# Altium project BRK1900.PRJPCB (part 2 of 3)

## Sheet Expansion-MC2.SchDoc: BRK1900 - Expansion MC2
size C; Organization: Opal Kelly; Address1: 13500 SW 72nd Ave STE 100; Address3: Portland, OR  97223; Address4: http://www.opalkelly.com; DocumentNumber: xxx; Revision: 1; SheetNumber: 3; SheetTotal: 9; PageSetup: Record=PageOptions¦CenterHorizontal=True¦CenterVertical=True¦PrintScale=0.52¦XCorrection=1.00¦YCorrection=1.00¦PrintKind=0¦BorderSize=5000000¦LeftOffset=0¦BottomOffset=0¦Orientation=2¦PaperLength=1000¦PaperWidth=1000¦Scale=100¦PaperSource=7¦PrintQuality=-4¦MediaType=1¦DitherType=10¦PaperKind=Letter¦PrintScaleMode=1
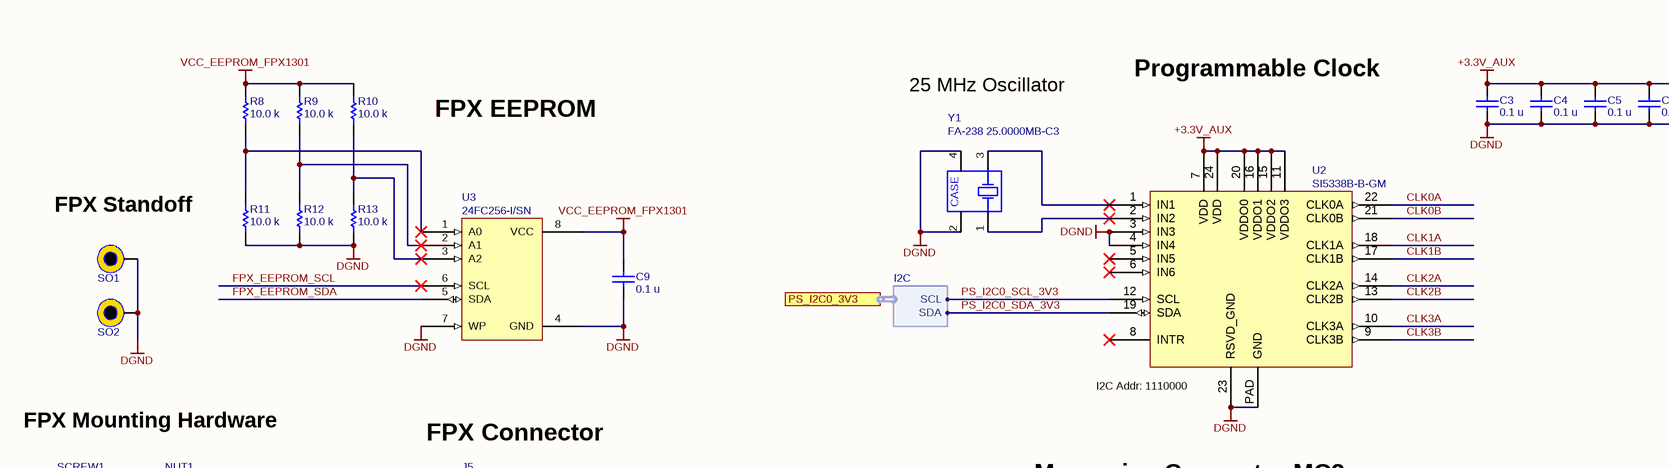
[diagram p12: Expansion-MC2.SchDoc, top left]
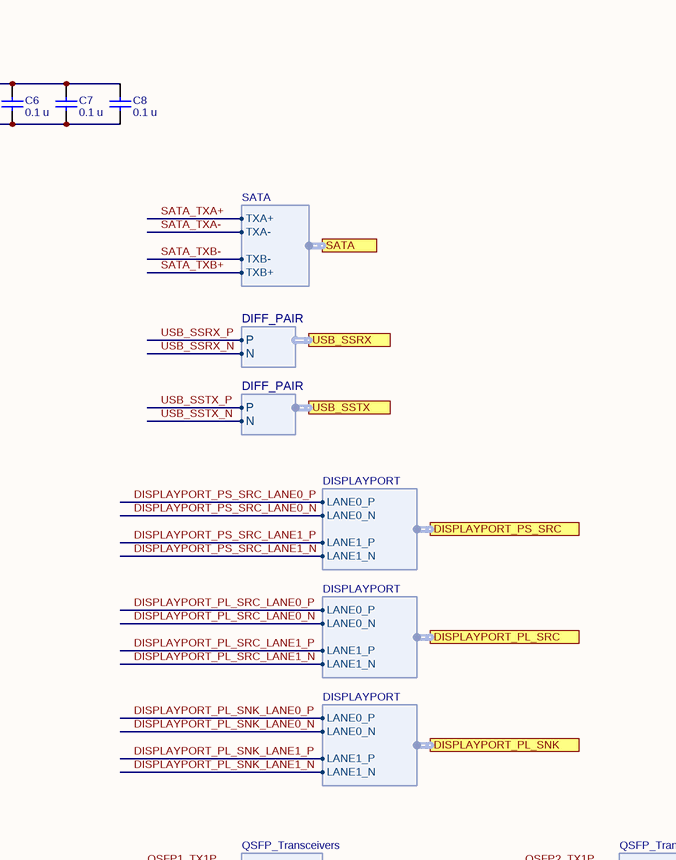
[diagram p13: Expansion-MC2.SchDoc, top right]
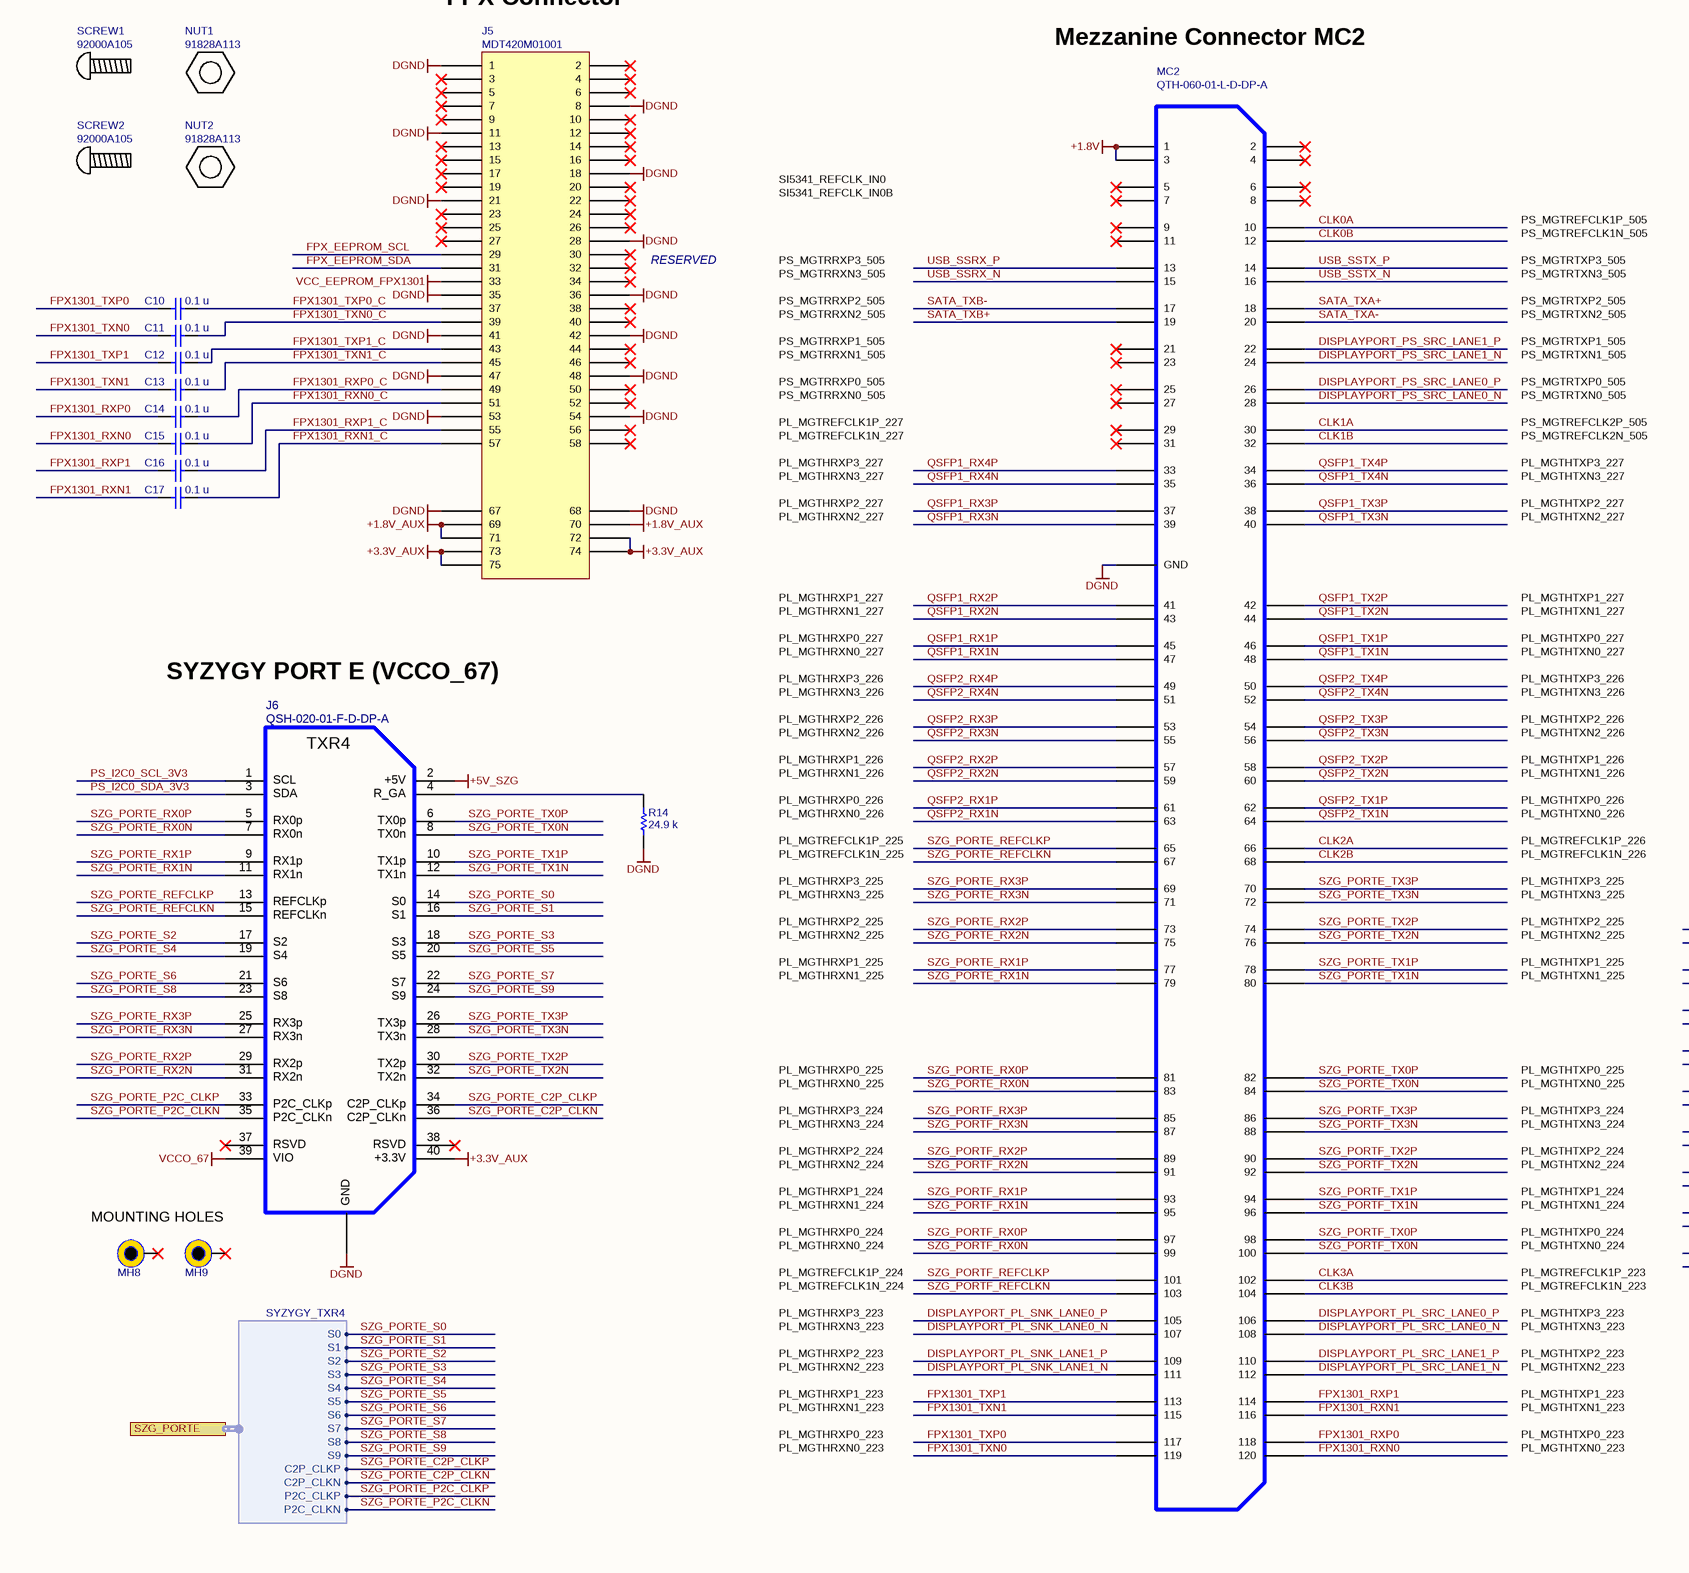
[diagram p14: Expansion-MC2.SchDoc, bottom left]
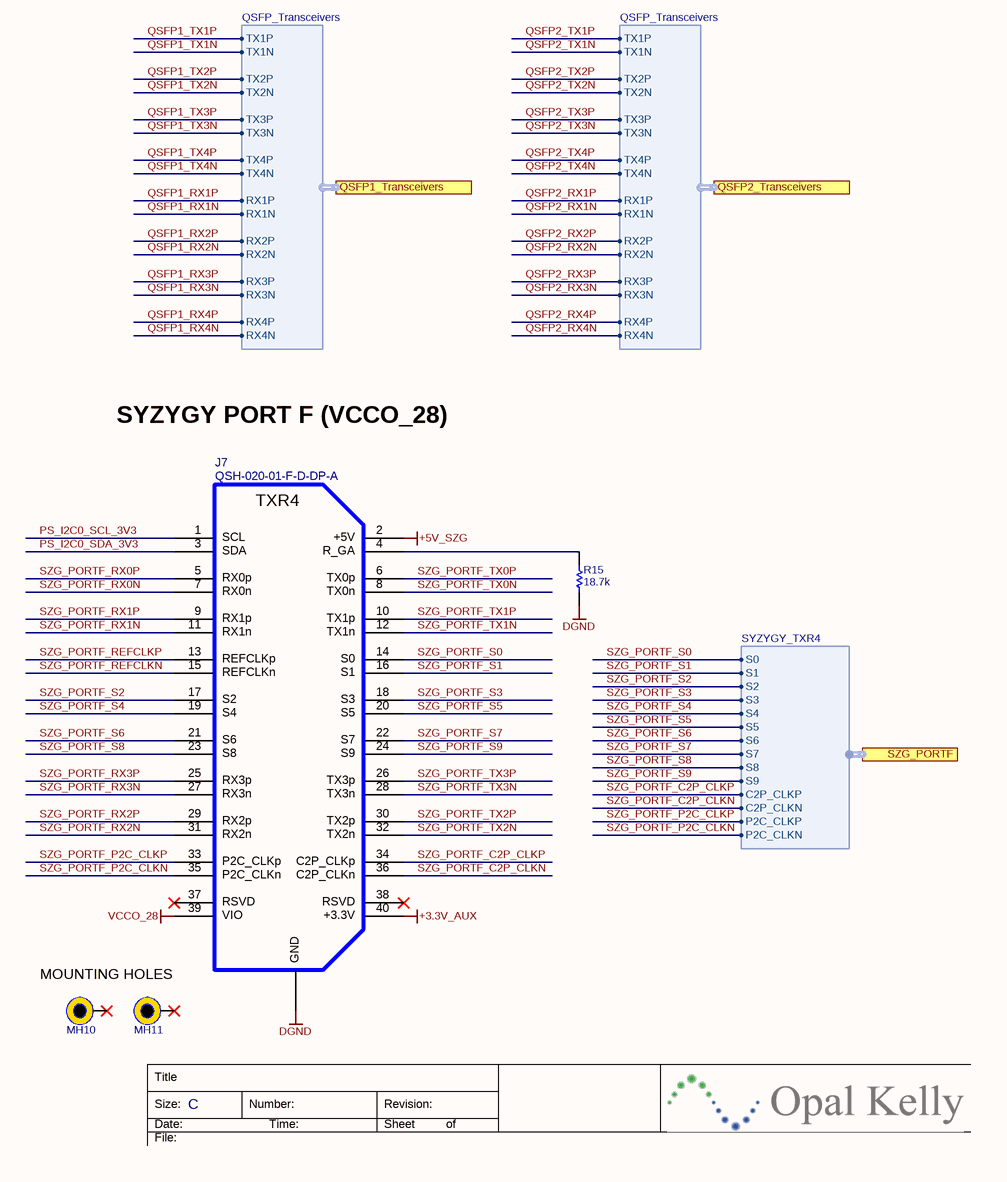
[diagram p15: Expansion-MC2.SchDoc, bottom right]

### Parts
C3  value 0.1 u  [CAPC1005X06A]  (hidden comment: C0402C104K8PACTU)
C4  value 0.1 u  [CAPC1005X06A]  (hidden comment: C0402C104K8PACTU)
C5  value 0.1 u  [CAPC1005X06A]  (hidden comment: C0402C104K8PACTU)
C6  value 0.1 u  [CAPC1005X06A]  (hidden comment: C0402C104K8PACTU)
C7  value 0.1 u  [CAPC1005X06A]  (hidden comment: C0402C104K8PACTU)
C8  value 0.1 u  [CAPC1005X06A]  (hidden comment: C0402C104K8PACTU)
C9  value 0.1 u  [CAPC1005X06A]  (hidden comment: C0402C104K8PACTU)
C10  value 0.1 u  [CAPC1005X06A]  (hidden comment: C0402C104K8PACTU)
C11  value 0.1 u  [CAPC1005X06A]  (hidden comment: C0402C104K8PACTU)
C12  value 0.1 u  [CAPC1005X06A]  (hidden comment: C0402C104K8PACTU)
C13  value 0.1 u  [CAPC1005X06A]  (hidden comment: C0402C104K8PACTU)
C14  value 0.1 u  [CAPC1005X06A]  (hidden comment: C0402C104K8PACTU)
C15  value 0.1 u  [CAPC1005X06A]  (hidden comment: C0402C104K8PACTU)
C16  value 0.1 u  [CAPC1005X06A]  (hidden comment: C0402C104K8PACTU)
C17  value 0.1 u  [CAPC1005X06A]  (hidden comment: C0402C104K8PACTU)
J5  MDT420M01001  [M2-Connector_M-Keying]
J6  QSH-020-01-F-D-DP-A  [QSH-020-01-X-D-DP-A-L]
J7  QSH-020-01-F-D-DP-A  [QSH-020-01-X-D-DP-A-L]
MC2  QTH-060-01-L-D-DP-A  [QTH-060-01-X-D-DP-A]
MH8  MTG  [MTG-2.7/5.0-PTH]  (value not drawn)
MH9  MTG  [MTG-2.7/5.0-PTH]  (value not drawn)
MH10  MTG  [MTG-2.7/5.0-PTH]  (value not drawn)
MH11  MTG  [MTG-2.7/5.0-PTH]  (value not drawn)
NUT1  91828A113  (mechanical)
NUT2  91828A113  (mechanical)
R8  value 10.0 k  [RESC1005X06A]  (hidden comment: CRCW040210K0FKED)
R9  value 10.0 k  [RESC1005X06A]  (hidden comment: CRCW040210K0FKED)
R10  value 10.0 k  [RESC1005X06A]  (hidden comment: CRCW040210K0FKED)
R11  value 10.0 k  [RESC1005X06A]  (hidden comment: CRCW040210K0FKED)
R12  value 10.0 k  [RESC1005X06A]  (hidden comment: CRCW040210K0FKED)
R13  value 10.0 k  [RESC1005X06A]  (hidden comment: CRCW040210K0FKED)
R14  value 24.9 k  [RESC1005X06A]  (hidden comment: CRCW040224K9FKED)
R15  value 18.7k  [RESC1005X06A]  (hidden comment: CRCW040218K7FKED)
SCREW1  92000A105  (mechanical)
SCREW2  92000A105  (mechanical)
SO1  Standoff  [9774025151R]  (value not drawn)
SO2  Standoff  [9774025151R]  (value not drawn)
U2  SI5338B-B-GM  [Si5338]
U3  24FC256-I/SN  [SO-G8]
Y1  FA-238 25.0000MB-C3  [OSC_SMD_32x25]

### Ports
DISPLAYPORT_PL_SNK (harness DISPLAYPORT), DISPLAYPORT_PL_SRC (harness DISPLAYPORT), DISPLAYPORT_PS_SRC (harness DISPLAYPORT), PS_I2C0_3V3 (harness I2C), QSFP1_Transceivers (harness QSFP_Transceivers), QSFP2_Transceivers (harness QSFP_Transceivers), SATA (harness SATA), SZG_PORTE (harness SYZYGY_TXR4), SZG_PORTF (harness SYZYGY_TXR4), USB_SSRX (harness DIFF_PAIR), USB_SSTX (harness DIFF_PAIR)

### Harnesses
QSFP_Transceivers: TX1P, TX1N, TX2P, TX2N, TX3P, TX3N, TX4P, TX4N, RX1P, RX1N, RX2P, RX2N, RX3P, RX3N, RX4P, RX4N
SATA: TXA+, TXA-, TXB-, TXB+
DIFF_PAIR: P, N
DISPLAYPORT: LANE0_P, LANE0_N, LANE1_P, LANE1_N
SYZYGY_TXR4: S0, S1, S2, S3, S4, S5, S6, S7, S8, S9, C2P_CLKP, C2P_CLKN, P2C_CLKP, P2C_CLKN
I2C: SCL, SDA

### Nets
+1.8V: MC2.1 MC2.3
+1.8V_AUX: J5.69 J5.70 J5.71
+3.3V_AUX: C3.2 C4.2 C5.2 C6.2 C7.2 C8.2 J5.72 J5.73 J5.74 J5.75 J6.40 J7.40 U2.7(VDD) U2.11(VDDO3) U2.15(VDDO2) U2.16(VDDO1) U2.20(VDDO0) U2.24(VDD)
+5V_SZG: J6.2 J7.2
DGND: C3.1 C4.1 C5.1 C6.1 C7.1 C8.1 C9.1 J5.1 J5.8 J5.11 J5.18 J5.21 J5.28 J5.35 J5.36 J5.41 J5.42 J5.47 J5.48 J5.53 J5.54 J5.67 J5.68 J6.0(GND) J7.0(GND) MC2.0(GND) R11.1 R12.1 R13.1 R14.1 R15.1 SO1.1 SO2.1 U2.3(IN3) U2.4(IN4) U2.23(RSVD_GND) U2.PAD(GND) U3.4(GND) U3.7(WP) Y1.2(CASE) Y1.4(CASE)
VCC_EEPROM_FPX1301: C9.2 J5.33 R8.2 R9.2 R10.2 U3.8(VCC)
VCCO_28: J7.39
VCCO_67: J6.39
CLK0A: MC2.10 U2.22(CLK0A)
CLK0B: MC2.12 U2.21(CLK0B)
CLK1A: MC2.30 U2.18(CLK1A)
CLK1B: MC2.32 U2.17(CLK1B)
CLK2A: MC2.66 U2.14(CLK2A)
CLK2B: MC2.68 U2.13(CLK2B)
CLK3A: MC2.102 U2.10(CLK3A)
CLK3B: MC2.104 U2.9(CLK3B)
DISPLAYPORT_PL_SNK_LANE0_N: MC2.107 ; port DISPLAYPORT_PL_SNK.LANE0_N
DISPLAYPORT_PL_SNK_LANE0_P: MC2.105 ; port DISPLAYPORT_PL_SNK.LANE0_P
DISPLAYPORT_PL_SNK_LANE1_N: MC2.111 ; port DISPLAYPORT_PL_SNK.LANE1_N
DISPLAYPORT_PL_SNK_LANE1_P: MC2.109 ; port DISPLAYPORT_PL_SNK.LANE1_P
DISPLAYPORT_PL_SRC_LANE0_N: MC2.108 ; port DISPLAYPORT_PL_SRC.LANE0_N
DISPLAYPORT_PL_SRC_LANE0_P: MC2.106 ; port DISPLAYPORT_PL_SRC.LANE0_P
DISPLAYPORT_PL_SRC_LANE1_N: MC2.112 ; port DISPLAYPORT_PL_SRC.LANE1_N
DISPLAYPORT_PL_SRC_LANE1_P: MC2.110 ; port DISPLAYPORT_PL_SRC.LANE1_P
DISPLAYPORT_PS_SRC_LANE0_N: MC2.28 ; port DISPLAYPORT_PS_SRC.LANE0_N
DISPLAYPORT_PS_SRC_LANE0_P: MC2.26 ; port DISPLAYPORT_PS_SRC.LANE0_P
DISPLAYPORT_PS_SRC_LANE1_N: MC2.24 ; port DISPLAYPORT_PS_SRC.LANE1_N
DISPLAYPORT_PS_SRC_LANE1_P: MC2.22 ; port DISPLAYPORT_PS_SRC.LANE1_P
FPX1301_RXN0: C15.1 MC2.120
FPX1301_RXN0_C: C15.2 J5.51
FPX1301_RXN1: C17.1 MC2.116
FPX1301_RXN1_C: C17.2 J5.57
FPX1301_RXP0: C14.1 MC2.118
FPX1301_RXP0_C: C14.2 J5.49
FPX1301_RXP1: C16.1 MC2.114
FPX1301_RXP1_C: C16.2 J5.55
FPX1301_TXN0: C11.1 MC2.119
FPX1301_TXN0_C: C11.2 J5.39
FPX1301_TXN1: C13.1 MC2.115
FPX1301_TXN1_C: C13.2 J5.45
FPX1301_TXP0: C10.1 MC2.117
FPX1301_TXP0_C: C10.2 J5.37
FPX1301_TXP1: C12.1 MC2.113
FPX1301_TXP1_C: C12.2 J5.43
FPX_EEPROM_SCL: J5.29 U3.6(SCL)
FPX_EEPROM_SDA: J5.31 U3.5(SDA)
PS_I2C0_SCL_3V3: J6.1 J7.1 U2.12(SCL) ; port PS_I2C0_3V3.SCL
PS_I2C0_SDA_3V3: J6.3 J7.3 U2.19(SDA) ; port PS_I2C0_3V3.SDA
QSFP1_RX1N: MC2.47 ; port QSFP1_Transceivers.RX1N
QSFP1_RX1P: MC2.45 ; port QSFP1_Transceivers.RX1P
QSFP1_RX2N: MC2.43 ; port QSFP1_Transceivers.RX2N
QSFP1_RX2P: MC2.41 ; port QSFP1_Transceivers.RX2P
QSFP1_RX3N: MC2.39 ; port QSFP1_Transceivers.RX3N
QSFP1_RX3P: MC2.37 ; port QSFP1_Transceivers.RX3P
QSFP1_RX4N: MC2.35 ; port QSFP1_Transceivers.RX4N
QSFP1_RX4P: MC2.33 ; port QSFP1_Transceivers.RX4P
QSFP1_TX1N: MC2.48 ; port QSFP1_Transceivers.TX1N
QSFP1_TX1P: MC2.46 ; port QSFP1_Transceivers.TX1P
QSFP1_TX2N: MC2.44 ; port QSFP1_Transceivers.TX2N
QSFP1_TX2P: MC2.42 ; port QSFP1_Transceivers.TX2P
QSFP1_TX3N: MC2.40 ; port QSFP1_Transceivers.TX3N
QSFP1_TX3P: MC2.38 ; port QSFP1_Transceivers.TX3P
QSFP1_TX4N: MC2.36 ; port QSFP1_Transceivers.TX4N
QSFP1_TX4P: MC2.34 ; port QSFP1_Transceivers.TX4P
QSFP2_RX1N: MC2.63 ; port QSFP2_Transceivers.RX1N
QSFP2_RX1P: MC2.61 ; port QSFP2_Transceivers.RX1P
QSFP2_RX2N: MC2.59 ; port QSFP2_Transceivers.RX2N
QSFP2_RX2P: MC2.57 ; port QSFP2_Transceivers.RX2P
QSFP2_RX3N: MC2.55 ; port QSFP2_Transceivers.RX3N
QSFP2_RX3P: MC2.53 ; port QSFP2_Transceivers.RX3P
QSFP2_RX4N: MC2.51 ; port QSFP2_Transceivers.RX4N
QSFP2_RX4P: MC2.49 ; port QSFP2_Transceivers.RX4P
QSFP2_TX1N: MC2.64 ; port QSFP2_Transceivers.TX1N
QSFP2_TX1P: MC2.62 ; port QSFP2_Transceivers.TX1P
QSFP2_TX2N: MC2.60 ; port QSFP2_Transceivers.TX2N
QSFP2_TX2P: MC2.58 ; port QSFP2_Transceivers.TX2P
QSFP2_TX3N: MC2.56 ; port QSFP2_Transceivers.TX3N
QSFP2_TX3P: MC2.54 ; port QSFP2_Transceivers.TX3P
QSFP2_TX4N: MC2.52 ; port QSFP2_Transceivers.TX4N
QSFP2_TX4P: MC2.50 ; port QSFP2_Transceivers.TX4P
SATA_TXA+: MC2.18 ; port SATA.TXA+
SATA_TXA-: MC2.20 ; port SATA.TXA-
SATA_TXB+: MC2.19 ; port SATA.TXB+
SATA_TXB-: MC2.17 ; port SATA.TXB-
SZG_PORTE_C2P_CLKN: J6.36 ; port SZG_PORTE.C2P_CLKN
SZG_PORTE_C2P_CLKP: J6.34 ; port SZG_PORTE.C2P_CLKP
SZG_PORTE_P2C_CLKN: J6.35 ; port SZG_PORTE.P2C_CLKN
SZG_PORTE_P2C_CLKP: J6.33 ; port SZG_PORTE.P2C_CLKP
SZG_PORTE_REFCLKN: J6.15 MC2.67
SZG_PORTE_REFCLKP: J6.13 MC2.65
SZG_PORTE_RX0N: J6.7 MC2.83
SZG_PORTE_RX0P: J6.5 MC2.81
SZG_PORTE_RX1N: J6.11 MC2.79
SZG_PORTE_RX1P: J6.9 MC2.77
SZG_PORTE_RX2N: J6.31 MC2.75
SZG_PORTE_RX2P: J6.29 MC2.73
SZG_PORTE_RX3N: J6.27 MC2.71
SZG_PORTE_RX3P: J6.25 MC2.69
SZG_PORTE_S0: J6.14 ; port SZG_PORTE.S0
SZG_PORTE_S1: J6.16 ; port SZG_PORTE.S1
SZG_PORTE_S2: J6.17 ; port SZG_PORTE.S2
SZG_PORTE_S3: J6.18 ; port SZG_PORTE.S3
SZG_PORTE_S4: J6.19 ; port SZG_PORTE.S4
SZG_PORTE_S5: J6.20 ; port SZG_PORTE.S5
SZG_PORTE_S6: J6.21 ; port SZG_PORTE.S6
SZG_PORTE_S7: J6.22 ; port SZG_PORTE.S7
SZG_PORTE_S8: J6.23 ; port SZG_PORTE.S8
SZG_PORTE_S9: J6.24 ; port SZG_PORTE.S9
SZG_PORTE_TX0N: J6.8 MC2.84
SZG_PORTE_TX0P: J6.6 MC2.82
SZG_PORTE_TX1N: J6.12 MC2.80
SZG_PORTE_TX1P: J6.10 MC2.78
SZG_PORTE_TX2N: J6.32 MC2.76
SZG_PORTE_TX2P: J6.30 MC2.74
SZG_PORTE_TX3N: J6.28 MC2.72
SZG_PORTE_TX3P: J6.26 MC2.70
SZG_PORTF_C2P_CLKN: J7.36 ; port SZG_PORTF.C2P_CLKN
SZG_PORTF_C2P_CLKP: J7.34 ; port SZG_PORTF.C2P_CLKP
SZG_PORTF_P2C_CLKN: J7.35 ; port SZG_PORTF.P2C_CLKN
SZG_PORTF_P2C_CLKP: J7.33 ; port SZG_PORTF.P2C_CLKP
SZG_PORTF_REFCLKN: J7.15 MC2.103
SZG_PORTF_REFCLKP: J7.13 MC2.101
SZG_PORTF_RX0N: J7.7 MC2.99
SZG_PORTF_RX0P: J7.5 MC2.97
SZG_PORTF_RX1N: J7.11 MC2.95
SZG_PORTF_RX1P: J7.9 MC2.93
SZG_PORTF_RX2N: J7.31 MC2.91
SZG_PORTF_RX2P: J7.29 MC2.89
SZG_PORTF_RX3N: J7.27 MC2.87
SZG_PORTF_RX3P: J7.25 MC2.85
SZG_PORTF_S0: J7.14 ; port SZG_PORTF.S0
SZG_PORTF_S1: J7.16 ; port SZG_PORTF.S1
SZG_PORTF_S2: J7.17 ; port SZG_PORTF.S2
SZG_PORTF_S3: J7.18 ; port SZG_PORTF.S3
SZG_PORTF_S4: J7.19 ; port SZG_PORTF.S4
SZG_PORTF_S5: J7.20 ; port SZG_PORTF.S5
SZG_PORTF_S6: J7.21 ; port SZG_PORTF.S6
SZG_PORTF_S7: J7.22 ; port SZG_PORTF.S7
SZG_PORTF_S8: J7.23 ; port SZG_PORTF.S8
SZG_PORTF_S9: J7.24 ; port SZG_PORTF.S9
SZG_PORTF_TX0N: J7.8 MC2.100
SZG_PORTF_TX0P: J7.6 MC2.98
SZG_PORTF_TX1N: J7.12 MC2.96
SZG_PORTF_TX1P: J7.10 MC2.94
SZG_PORTF_TX2N: J7.32 MC2.92
SZG_PORTF_TX2P: J7.30 MC2.90
SZG_PORTF_TX3N: J7.28 MC2.88
SZG_PORTF_TX3P: J7.26 MC2.86
USB_SSRX_N: MC2.15 ; port USB_SSRX.N
USB_SSRX_P: MC2.13 ; port USB_SSRX.P
USB_SSTX_N: MC2.16 ; port USB_SSTX.N
USB_SSTX_P: MC2.14 ; port USB_SSTX.P
NetJ6_4: J6.4 R14.2
NetJ7_4: J7.4 R15.2
NetR8_1: R8.1 R11.2 U3.1(A0)
NetR9_1: R9.1 R12.2 U3.2(A1)
NetR10_1: R10.1 R13.2 U3.3(A2)
NetU2_1: U2.1(IN1) Y1.3(OSC2)
NetU2_2: U2.2(IN2) Y1.1(OSC1)

Not connected (* = marked no-connect by the designer): J5 2* 3* 4* 5* 6* 7* 9* 10* 12* 13* 14* 15* 16* 17* 19* 20* 22* 23* 24* 25* 26* 27* 30* 32* 34* 38* 40* 44* 46* 50* 52* 56* 58*; J6 37* 38*; J7 37* 38*; MC2 2* 4* 5* 6* 7* 8* 9* 11* 21* 23* 25* 27* 29* 31*; MH8 1*; MH9 1*; MH10 1*; MH11 1*; U2 5(IN5)* 6(IN6)* 8(INTR)*

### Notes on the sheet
- Programmable Clock
- FPX EEPROM
- 25 MHz Oscillator
- FPX Standoff
- (near U2) I2C Addr: 1110000
- FPX Mounting Hardware
- FPX Connector
- Mezzanine Connector MC2
- SI5341_REFCLK_IN0
- SI5341_REFCLK_IN0B
- PS_MGTREFCLK1P_505
- PS_MGTREFCLK1N_505
- RESERVED
- PS_MGTRRXP3_505
- PS_MGTRRXN3_505
- PS_MGTRRXP2_505
- PS_MGTRRXN2_505
- PS_MGTRTXP3_505
- PS_MGTRTXN3_505
- PS_MGTRTXP2_505
- PS_MGTRTXN2_505
- PS_MGTRRXP1_505
- PS_MGTRRXN1_505
- PS_MGTRRXP0_505
- PS_MGTRTXP1_505
- PS_MGTRTXN1_505
- PS_MGTRTXP0_505
- PS_MGTRRXN0_505
- PL_MGTREFCLK1P_227
- PL_MGTREFCLK1N_227
- PS_MGTRTXN0_505
- PS_MGTREFCLK2P_505
- PS_MGTREFCLK2N_505
- PL_MGTHRXP3_227
- PL_MGTHRXN3_227
- PL_MGTHRXP2_227
- PL_MGTHRXN2_227
- PL_MGTHTXP3_227
- PL_MGTHTXN3_227
- PL_MGTHTXP2_227
- PL_MGTHTXN2_227
- PL_MGTHRXN1_227
- PL_MGTHRXP1_227
- PL_MGTHRXP0_227
- PL_MGTHRXN0_227
- PL_MGTHTXP1_227
- PL_MGTHTXN1_227
- PL_MGTHTXP0_227
- PL_MGTHTXN0_227
- SYZYGY PORT E (VCCO_67)
- PL_MGTHRXP3_226
- PL_MGTHRXN3_226
- PL_MGTHRXP2_226
- PL_MGTHTXP3_226
- PL_MGTHTXN3_226
- PL_MGTHTXP2_226
- PL_MGTHRXN2_226
- PL_MGTHRXP1_226
- PL_MGTHRXN1_226
- PL_MGTHTXN2_226
- PL_MGTHTXP1_226
- PL_MGTHTXN1_226
- PL_MGTHRXP0_226
- PL_MGTHRXN0_226
- PL_MGTREFCLK1P_225
- PL_MGTREFCLK1N_225
- PL_MGTHTXP0_226
- PL_MGTHTXN0_226
- PL_MGTREFCLK1P_226
- PL_MGTREFCLK1N_226
- SYZYGY PORT F (VCCO_28)
- PL_MGTHRXP3_225
- PL_MGTHRXN3_225
- PL_MGTHRXP2_225
- PL_MGTHTXP3_225
- PL_MGTHTXN3_225
- PL_MGTHTXP2_225
- PL_MGTHRXN2_225
- PL_MGTHRXP1_225
- PL_MGTHRXN1_225
- PL_MGTHTXN2_225
- PL_MGTHTXP1_225
- PL_MGTHTXN1_225
- PL_MGTHRXP0_225
- PL_MGTHRXN0_225
- PL_MGTHRXP3_224
- PL_MGTHRXN3_224
- PL_MGTHTXP0_225
- PL_MGTHTXN0_225
- PL_MGTHTXP3_224
- PL_MGTHTXN3_224
- PL_MGTHRXP2_224
- PL_MGTHRXN2_224
- PL_MGTHRXP1_224
- PL_MGTHTXP2_224
- PL_MGTHTXN2_224
- PL_MGTHTXP1_224
- MOUNTING HOLES
- PL_MGTHRXN1_224
- PL_MGTHRXP0_224
- PL_MGTHRXN0_224
- PL_MGTHTXN1_224
- PL_MGTHTXP0_224
- PL_MGTHTXN0_224
- PL_MGTREFCLK1P_224
- PL_MGTREFCLK1N_224
- PL_MGTHRXP3_223
- PL_MGTHRXN3_223
- PL_MGTREFCLK1P_223
- PL_MGTREFCLK1N_223
- PL_MGTHTXP3_223
- PL_MGTHTXN3_223
- PL_MGTHRXP2_223
- PL_MGTHRXN2_223
- PL_MGTHRXP1_223
- PL_MGTHTXP2_223
- PL_MGTHTXN2_223
- PL_MGTHTXP1_223
- PL_MGTHRXN1_223
- PL_MGTHRXP0_223
- PL_MGTHRXN0_223
- PL_MGTHTXN1_223
- PL_MGTHTXP0_223
- PL_MGTHTXN0_223
- Title
- Size:
- Date:
- File:
- C
- Number:
- Time:
- Revision:
- Sheet
- of

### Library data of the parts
C3-C8 C10-C17 = 000070: Partnumber: 000070; manufacturer: Kemet; ValueFloat: 1E-7; x_tolerance: 10
C9 = 000070: Ceramic capacitor; Partnumber: 000070; manufacturer: Kemet; ValueFloat: 1E-7; x_tolerance: 10
J5 = 001722: M.2 (NGFF) edge card connector, 4.2 mm height, M keying; Partnumber: 001722; manufacturer: Amphenol
J6 J7 = 000694: 0.5mm hi-speed, high-density socket (male); Partnumber: 000694; manufacturer: Samtec
MC2 = 001769: Partnumber: 001769; manufacturer: Samtec
MH8-MH11 = MTG: Mounting hole; partnumber: ALIGNI_IGNORE
NUT1 NUT2 = NUT: M2.5 hex nut; Manufacturer: McMaster-Carr; partnumber: 001810
R8-R13 = 001521: Thick-film resistor; Partnumber: 001521; manufacturer: Vishay; ValueFloat: 10000; x_tolerance: 1
R14 = 000934: Partnumber: 000934; manufacturer: Vishay; ValueFloat: 24900; x_tolerance: 1
R15 = 001783: Partnumber: 001783; manufacturer: Vishay; ValueFloat: 18700; x_tolerance: 1
SCREW1 SCREW2 = SCREW: Metric Pan Head Phil Machine Screw; Manufacturer: McMaster-Carr; partnumber: 001811
SO1 SO2 = 001726: Mounting hole; Partnumber: 001726; manufacturer: Wurth; id: 224568; inventory_price: 0.75
U2 = 001741: Partnumber: 001741; manufacturer: Silicon Labs
U3 = 000842: EEPROM; Partnumber: 000842; manufacturer: Microchip
Y1 = 001742: Partnumber: 001742; manufacturer: Epson

## Sheet Expansion-MC3.SchDoc: BRK1900 - Expansion MC3
size C; Organization: Opal Kelly; Address1: 13500 SW 72nd Ave STE 100; Address3: Portland, OR  97223; Address4: http://www.opalkelly.com; DocumentNumber: xxx; Revision: 1; SheetNumber: 4; SheetTotal: 9; PageSetup: Record=PageOptions¦CenterHorizontal=True¦CenterVertical=True¦PrintScale=0.52¦XCorrection=1.00¦YCorrection=1.00¦PrintKind=0¦BorderSize=5000000¦LeftOffset=0¦BottomOffset=0¦Orientation=2¦PaperLength=1000¦PaperWidth=1000¦Scale=100¦PaperSource=7¦PrintQuality=-4¦MediaType=1¦DitherType=10¦PaperKind=Letter¦PrintScaleMode=1
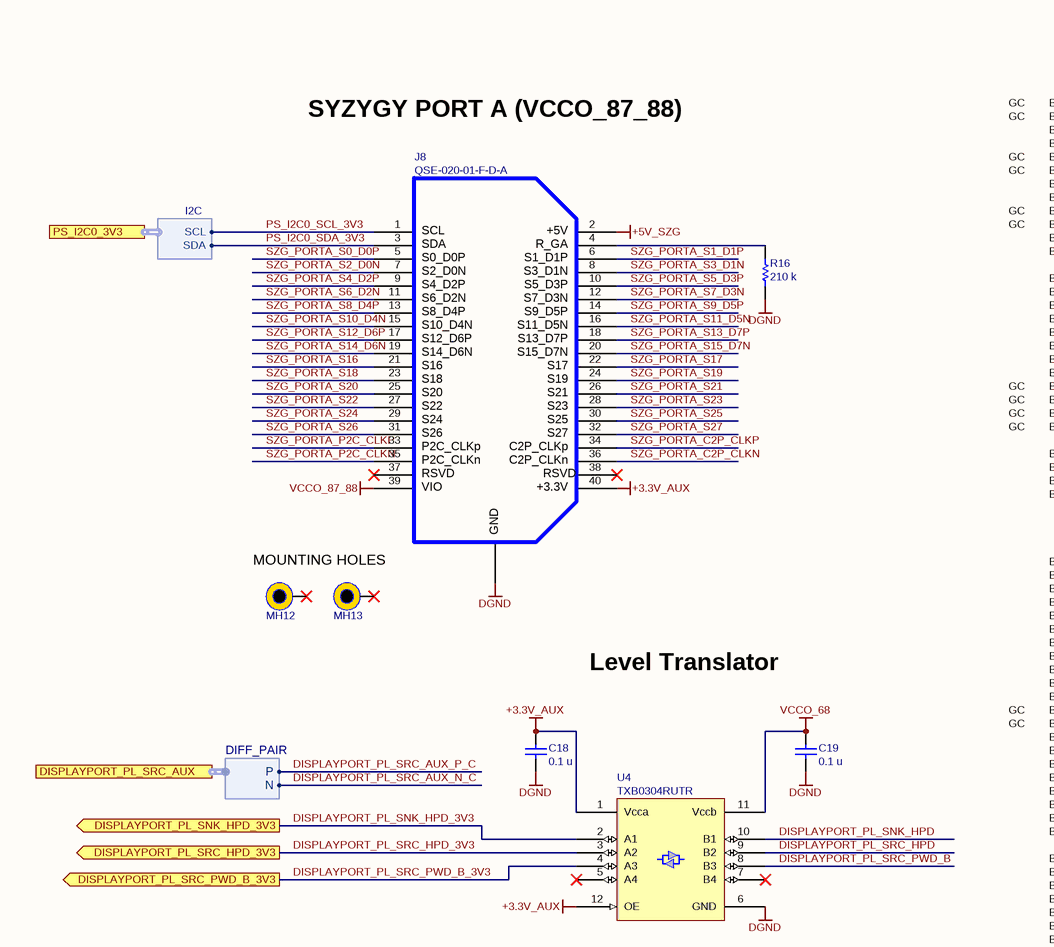
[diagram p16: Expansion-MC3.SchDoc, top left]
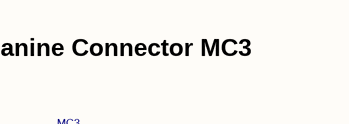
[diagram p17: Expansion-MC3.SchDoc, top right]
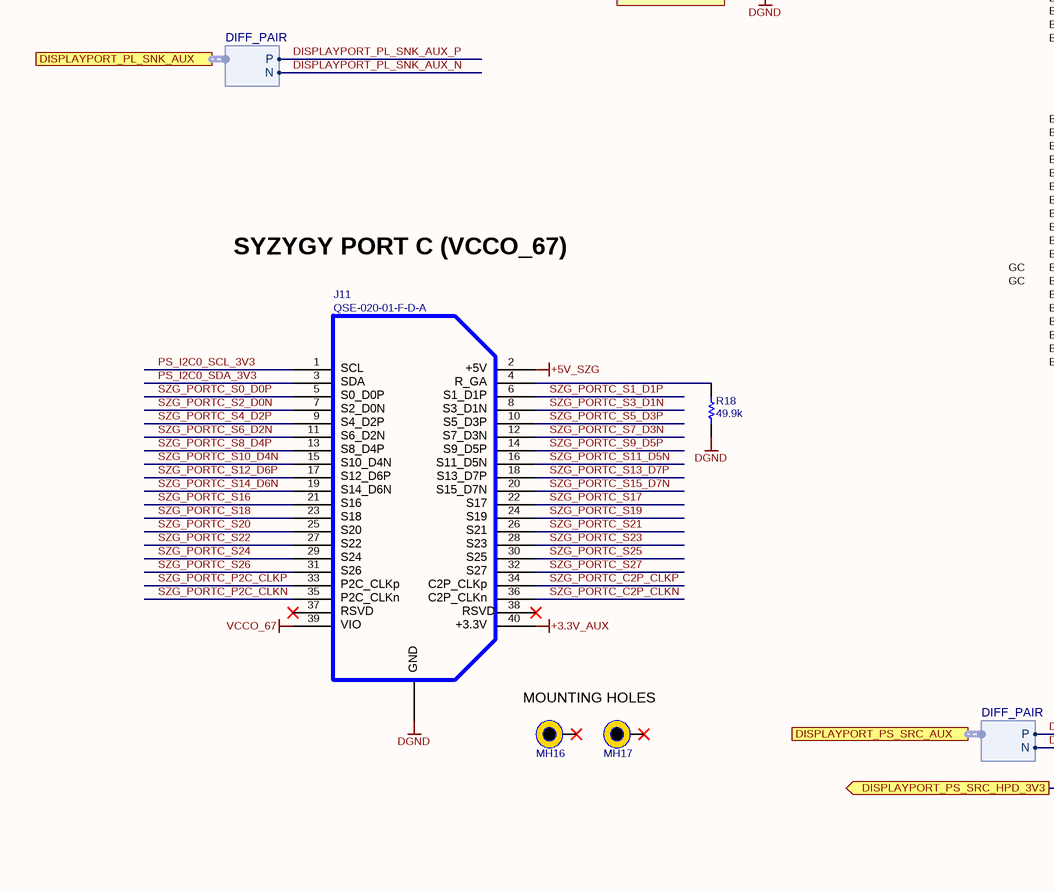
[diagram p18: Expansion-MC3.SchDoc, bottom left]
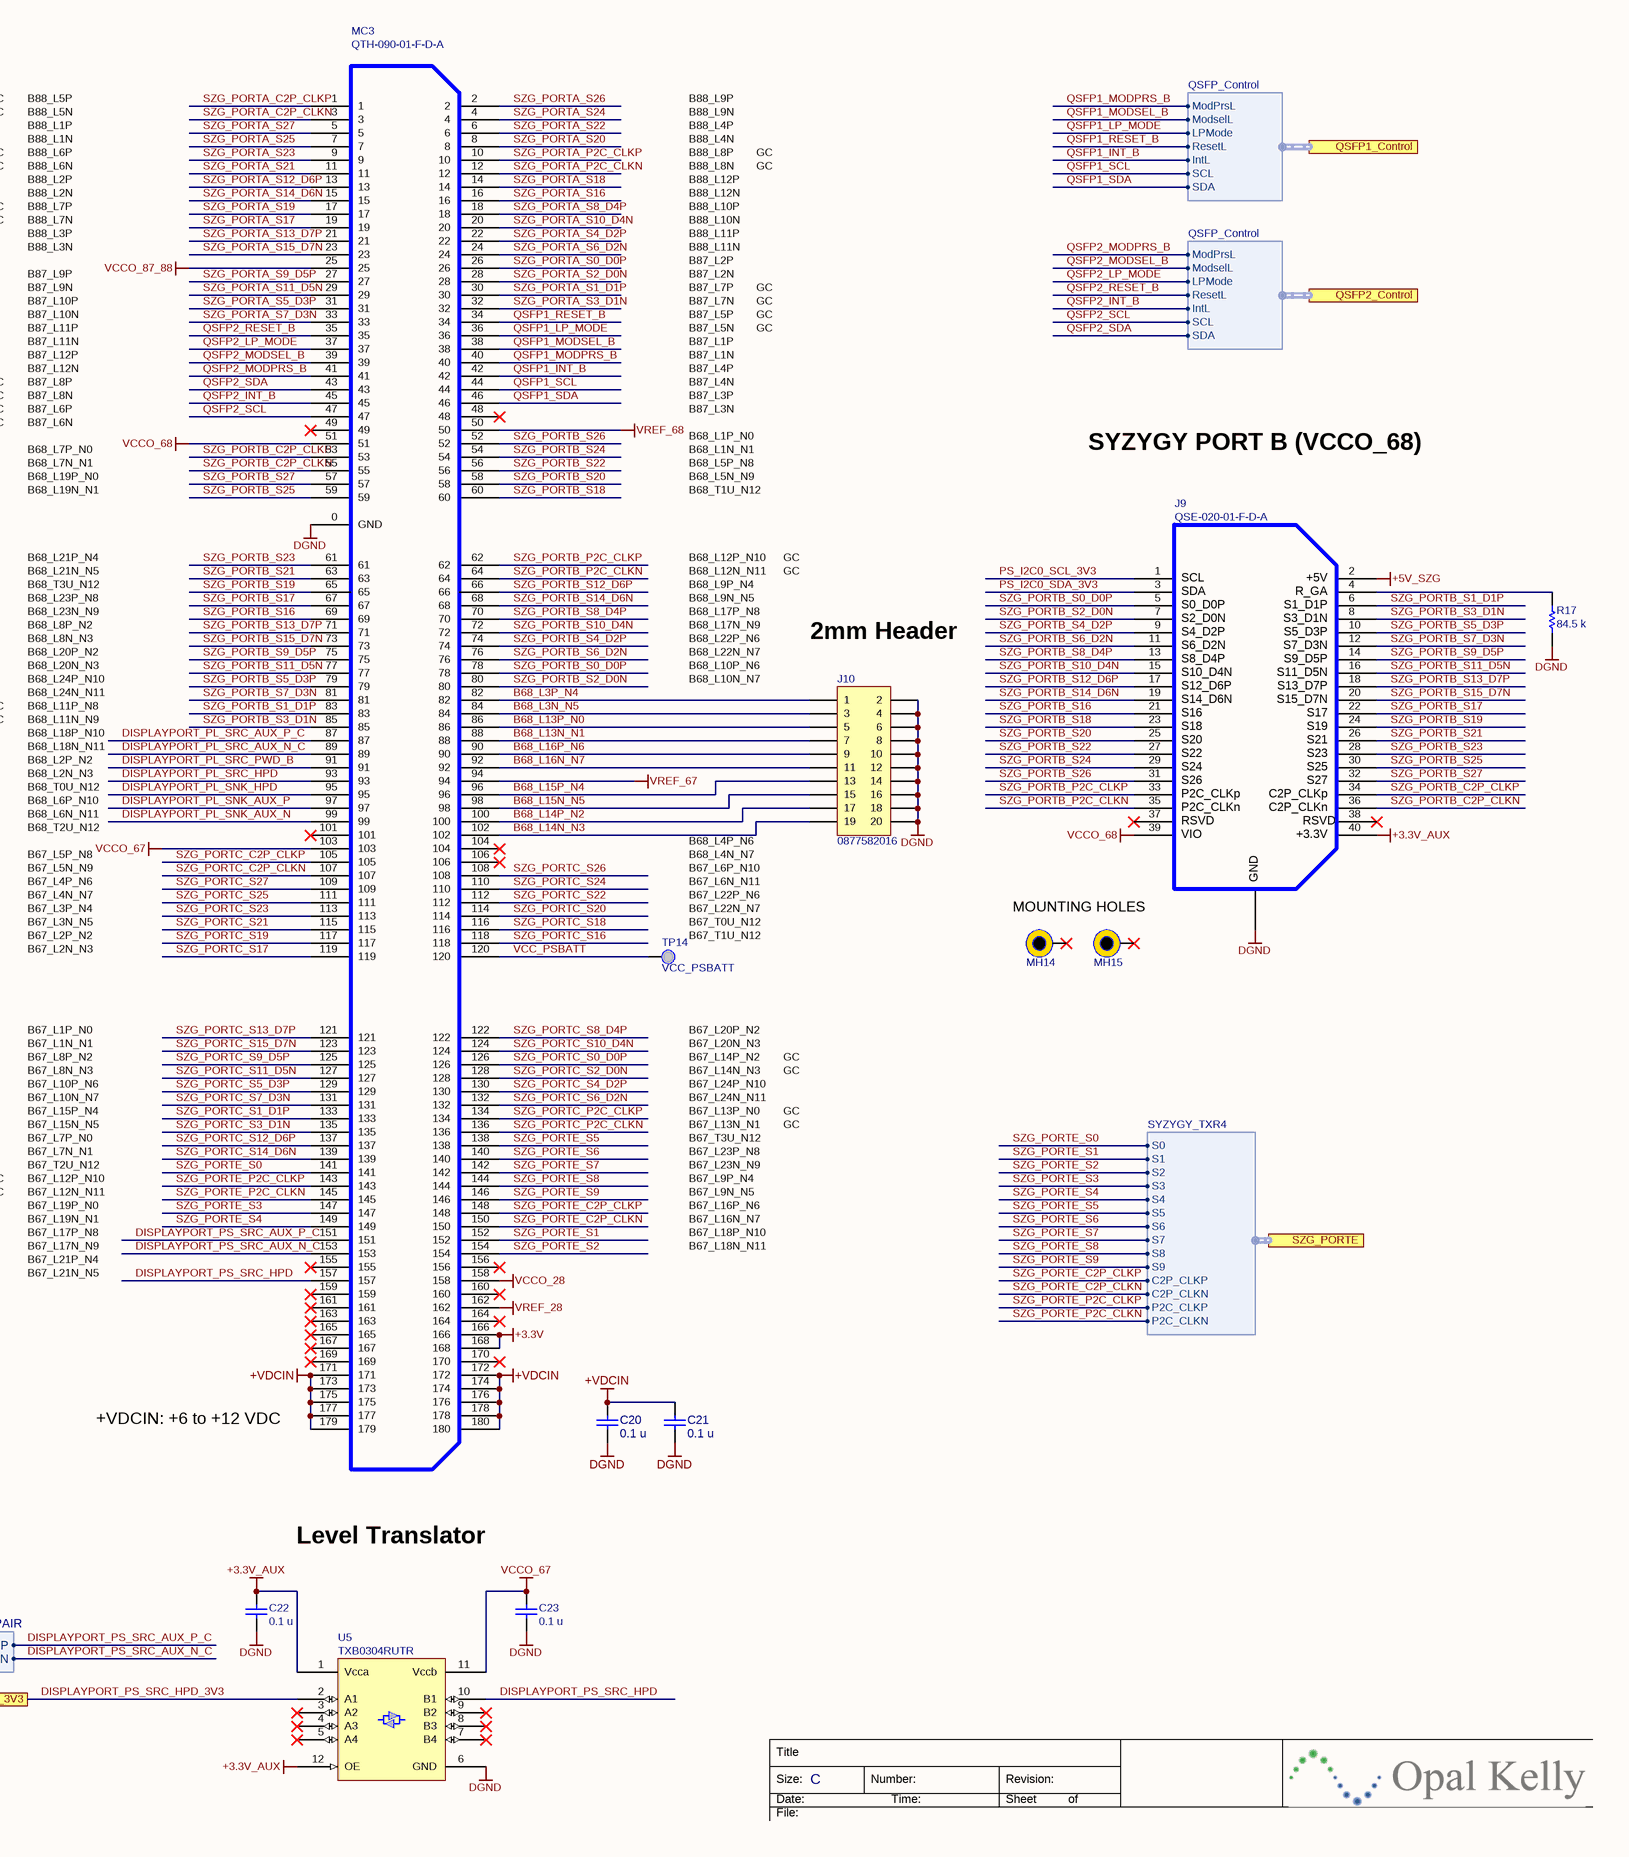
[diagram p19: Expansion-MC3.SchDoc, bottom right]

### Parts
C18  value 0.1 u  [CAPC1005X06A]  (hidden comment: C0402C104K8PACTU)
C19  value 0.1 u  [CAPC1005X06A]  (hidden comment: C0402C104K8PACTU)
C20  value 0.1 u  [CAPC1005X06A]  (hidden comment: TMK105BJ104KV-F)
C21  value 0.1 u  [CAPC1005X06A]  (hidden comment: TMK105BJ104KV-F)
C22  value 0.1 u  [CAPC1005X06A]  (hidden comment: C0402C104K8PACTU)
C23  value 0.1 u  [CAPC1005X06A]  (hidden comment: C0402C104K8PACTU)
J8  QSE-020-01-F-D-A  [QSE-020-01-X-D-A-L]
J9  QSE-020-01-F-D-A  [QSE-020-01-X-D-A-L]
J10  0877582016  [HDR2X10-2MM]
J11  QSE-020-01-F-D-A  [QSE-020-01-X-D-A-L]
MC3  QTH-090-01-F-D-A  [QTH-090-01-X-D]
MH12  MTG  [MTG-2.7/5.0-PTH]  (value not drawn)
MH13  MTG  [MTG-2.7/5.0-PTH]  (value not drawn)
MH14  MTG  [MTG-2.7/5.0-PTH]  (value not drawn)
MH15  MTG  [MTG-2.7/5.0-PTH]  (value not drawn)
MH16  MTG  [MTG-2.7/5.0-PTH]  (value not drawn)
MH17  MTG  [MTG-2.7/5.0-PTH]  (value not drawn)
R16  value 210 k  [RESC1005X06A]  (hidden comment: CRCW0402210KFKED)
R17  value 84.5 k  [RESC1005X06A]  (hidden comment: CRCW040284K5FKED)
R18  value 49.9k  [RESC1005X06A]  (hidden comment: CRCW040249K9FKED)
TP14  VCC_PSBATT  [TP-PTH-25/45]
U4  TXB0304RUTR  [PUQFN-N12]
U5  TXB0304RUTR  [PUQFN-N12]

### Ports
DISPLAYPORT_PL_SNK_AUX (harness DIFF_PAIR), DISPLAYPORT_PL_SNK_HPD_3V3 (out), DISPLAYPORT_PL_SRC_AUX (harness DIFF_PAIR), DISPLAYPORT_PL_SRC_HPD_3V3 (out), DISPLAYPORT_PL_SRC_PWD_B_3V3 (out), DISPLAYPORT_PS_SRC_AUX (harness DIFF_PAIR), DISPLAYPORT_PS_SRC_HPD_3V3 (out), PS_I2C0_3V3 (harness I2C), QSFP1_Control (harness QSFP_Control), QSFP2_Control (harness QSFP_Control), SZG_PORTE (harness SYZYGY_TXR4)

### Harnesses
SYZYGY_TXR4: S0, S1, S2, S3, S4, S5, S6, S7, S8, S9, C2P_CLKP, C2P_CLKN, P2C_CLKP, P2C_CLKN
I2C: SCL, SDA
QSFP_Control: ModPrsL, IntL, LPMode, ModselL, ResetL, SCL, SDA
DIFF_PAIR: P, N

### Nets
+3.3V: MC3.166 MC3.168
+3.3V_AUX: C18.2 C22.2 J8.40 J9.40 J11.40 U4.1(Vcca) U4.12(OE) U5.1(Vcca) U5.12(OE)
+5V_SZG: J8.2 J9.2 J11.2
+VDCIN: C20.1 C21.1 MC3.171 MC3.172 MC3.173 MC3.174 MC3.175 MC3.176 MC3.177 MC3.178 MC3.179 MC3.180
DGND: C18.1 C19.1 C20.2 C21.2 C22.1 C23.1 J8.0 J9.0 J10.2 J10.4 J10.6 J10.8 J10.10 J10.12 J10.14 J10.16 J10.18 J10.20 J11.0 MC3.0(GND) R16.1 R17.1 R18.1 U4.6(GND) U5.6(GND)
VCCO_28: MC3.158
VCCO_67: C23.2 J11.39 MC3.103 U5.11(Vccb)
VCCO_68: C19.2 J9.39 MC3.51 U4.11(Vccb)
VCCO_87_88: J8.39 MC3.25
VREF_28: MC3.162
VREF_67: MC3.94
VREF_68: MC3.50
B68_L3N_N5: J10.3 MC3.84
B68_L3P_N4: J10.1 MC3.82
B68_L13N_N1: J10.7 MC3.88
B68_L13P_N0: J10.5 MC3.86
B68_L14N_N3: J10.19 MC3.102
B68_L14P_N2: J10.17 MC3.100
B68_L15N_N5: J10.15 MC3.98
B68_L15P_N4: J10.13 MC3.96
B68_L16N_N7: J10.11 MC3.92
B68_L16P_N6: J10.9 MC3.90
DISPLAYPORT_PL_SNK_AUX_N: MC3.99 ; port DISPLAYPORT_PL_SNK_AUX.N
DISPLAYPORT_PL_SNK_AUX_P: MC3.97 ; port DISPLAYPORT_PL_SNK_AUX.P
DISPLAYPORT_PL_SNK_HPD: MC3.95 U4.10(B1)
DISPLAYPORT_PL_SNK_HPD_3V3: U4.2(A1) ; port DISPLAYPORT_PL_SNK_HPD_3V3
DISPLAYPORT_PL_SRC_AUX_N_C: MC3.89 ; port DISPLAYPORT_PL_SRC_AUX.N
DISPLAYPORT_PL_SRC_AUX_P_C: MC3.87 ; port DISPLAYPORT_PL_SRC_AUX.P
DISPLAYPORT_PL_SRC_HPD: MC3.93 U4.9(B2)
DISPLAYPORT_PL_SRC_HPD_3V3: U4.3(A2) ; port DISPLAYPORT_PL_SRC_HPD_3V3
DISPLAYPORT_PL_SRC_PWD_B: MC3.91 U4.8(B3)
DISPLAYPORT_PL_SRC_PWD_B_3V3: U4.4(A3) ; port DISPLAYPORT_PL_SRC_PWD_B_3V3
DISPLAYPORT_PS_SRC_AUX_N_C: MC3.153 ; port DISPLAYPORT_PS_SRC_AUX.N
DISPLAYPORT_PS_SRC_AUX_P_C: MC3.151 ; port DISPLAYPORT_PS_SRC_AUX.P
DISPLAYPORT_PS_SRC_HPD: MC3.157 U5.10(B1)
DISPLAYPORT_PS_SRC_HPD_3V3: U5.2(A1) ; port DISPLAYPORT_PS_SRC_HPD_3V3
PS_I2C0_SCL_3V3: J8.1 J9.1 J11.1 ; port PS_I2C0_3V3.SCL
PS_I2C0_SDA_3V3: J8.3 J9.3 J11.3 ; port PS_I2C0_3V3.SDA
QSFP1_INT_B: MC3.42 ; port QSFP1_Control.IntL
QSFP1_LP_MODE: MC3.36 ; port QSFP1_Control.LPMode
QSFP1_MODPRS_B: MC3.40 ; port QSFP1_Control.ModPrsL
QSFP1_MODSEL_B: MC3.38 ; port QSFP1_Control.ModselL
QSFP1_RESET_B: MC3.34 ; port QSFP1_Control.ResetL
QSFP1_SCL: MC3.44 ; port QSFP1_Control.SCL
QSFP1_SDA: MC3.46 ; port QSFP1_Control.SDA
QSFP2_INT_B: MC3.45 ; port QSFP2_Control.IntL
QSFP2_LP_MODE: MC3.37 ; port QSFP2_Control.LPMode
QSFP2_MODPRS_B: MC3.41 ; port QSFP2_Control.ModPrsL
QSFP2_MODSEL_B: MC3.39 ; port QSFP2_Control.ModselL
QSFP2_RESET_B: MC3.35 ; port QSFP2_Control.ResetL
QSFP2_SCL: MC3.47 ; port QSFP2_Control.SCL
QSFP2_SDA: MC3.43 ; port QSFP2_Control.SDA
SZG_PORTA_C2P_CLKN: J8.36 MC3.3
SZG_PORTA_C2P_CLKP: J8.34 MC3.1
SZG_PORTA_P2C_CLKN: J8.35 MC3.12
SZG_PORTA_P2C_CLKP: J8.33 MC3.10
SZG_PORTA_S0_D0P: J8.5 MC3.26
SZG_PORTA_S1_D1P: J8.6 MC3.30
SZG_PORTA_S2_D0N: J8.7 MC3.28
SZG_PORTA_S3_D1N: J8.8 MC3.32
SZG_PORTA_S4_D2P: J8.9 MC3.22
SZG_PORTA_S5_D3P: J8.10 MC3.31
SZG_PORTA_S6_D2N: J8.11 MC3.24
SZG_PORTA_S7_D3N: J8.12 MC3.33
SZG_PORTA_S8_D4P: J8.13 MC3.18
SZG_PORTA_S9_D5P: J8.14 MC3.27
SZG_PORTA_S10_D4N: J8.15 MC3.20
SZG_PORTA_S11_D5N: J8.16 MC3.29
SZG_PORTA_S12_D6P: J8.17 MC3.13
SZG_PORTA_S13_D7P: J8.18 MC3.21
SZG_PORTA_S14_D6N: J8.19 MC3.15
SZG_PORTA_S15_D7N: J8.20 MC3.23
SZG_PORTA_S16: J8.21 MC3.16
SZG_PORTA_S17: J8.22 MC3.19
SZG_PORTA_S18: J8.23 MC3.14
SZG_PORTA_S19: J8.24 MC3.17
SZG_PORTA_S20: J8.25 MC3.8
SZG_PORTA_S21: J8.26 MC3.11
SZG_PORTA_S22: J8.27 MC3.6
SZG_PORTA_S23: J8.28 MC3.9
SZG_PORTA_S24: J8.29 MC3.4
SZG_PORTA_S25: J8.30 MC3.7
SZG_PORTA_S26: J8.31 MC3.2
SZG_PORTA_S27: J8.32 MC3.5
SZG_PORTB_C2P_CLKN: J9.36 MC3.55
SZG_PORTB_C2P_CLKP: J9.34 MC3.53
SZG_PORTB_P2C_CLKN: J9.35 MC3.64
SZG_PORTB_P2C_CLKP: J9.33 MC3.62
SZG_PORTB_S0_D0P: J9.5 MC3.78
SZG_PORTB_S1_D1P: J9.6 MC3.83
SZG_PORTB_S2_D0N: J9.7 MC3.80
SZG_PORTB_S3_D1N: J9.8 MC3.85
SZG_PORTB_S4_D2P: J9.9 MC3.74
SZG_PORTB_S5_D3P: J9.10 MC3.79
SZG_PORTB_S6_D2N: J9.11 MC3.76
SZG_PORTB_S7_D3N: J9.12 MC3.81
SZG_PORTB_S8_D4P: J9.13 MC3.70
SZG_PORTB_S9_D5P: J9.14 MC3.75
SZG_PORTB_S10_D4N: J9.15 MC3.72
SZG_PORTB_S11_D5N: J9.16 MC3.77
SZG_PORTB_S12_D6P: J9.17 MC3.66
SZG_PORTB_S13_D7P: J9.18 MC3.71
SZG_PORTB_S14_D6N: J9.19 MC3.68
SZG_PORTB_S15_D7N: J9.20 MC3.73
SZG_PORTB_S16: J9.21 MC3.69
SZG_PORTB_S17: J9.22 MC3.67
SZG_PORTB_S18: J9.23 MC3.60
SZG_PORTB_S19: J9.24 MC3.65
SZG_PORTB_S20: J9.25 MC3.58
SZG_PORTB_S21: J9.26 MC3.63
SZG_PORTB_S22: J9.27 MC3.56
SZG_PORTB_S23: J9.28 MC3.61
SZG_PORTB_S24: J9.29 MC3.54
SZG_PORTB_S25: J9.30 MC3.59
SZG_PORTB_S26: J9.31 MC3.52
SZG_PORTB_S27: J9.32 MC3.57
SZG_PORTC_C2P_CLKN: J11.36 MC3.107
SZG_PORTC_C2P_CLKP: J11.34 MC3.105
SZG_PORTC_P2C_CLKN: J11.35 MC3.136
SZG_PORTC_P2C_CLKP: J11.33 MC3.134
SZG_PORTC_S0_D0P: J11.5 MC3.126
SZG_PORTC_S1_D1P: J11.6 MC3.133
SZG_PORTC_S2_D0N: J11.7 MC3.128
SZG_PORTC_S3_D1N: J11.8 MC3.135
SZG_PORTC_S4_D2P: J11.9 MC3.130
SZG_PORTC_S5_D3P: J11.10 MC3.129
SZG_PORTC_S6_D2N: J11.11 MC3.132
SZG_PORTC_S7_D3N: J11.12 MC3.131
SZG_PORTC_S8_D4P: J11.13 MC3.122
SZG_PORTC_S9_D5P: J11.14 MC3.125
SZG_PORTC_S10_D4N: J11.15 MC3.124
SZG_PORTC_S11_D5N: J11.16 MC3.127
SZG_PORTC_S12_D6P: J11.17 MC3.137
SZG_PORTC_S13_D7P: J11.18 MC3.121
SZG_PORTC_S14_D6N: J11.19 MC3.139
SZG_PORTC_S15_D7N: J11.20 MC3.123
SZG_PORTC_S16: J11.21 MC3.118
SZG_PORTC_S17: J11.22 MC3.119
SZG_PORTC_S18: J11.23 MC3.116
SZG_PORTC_S19: J11.24 MC3.117
SZG_PORTC_S20: J11.25 MC3.114
SZG_PORTC_S21: J11.26 MC3.115
SZG_PORTC_S22: J11.27 MC3.112
SZG_PORTC_S23: J11.28 MC3.113
SZG_PORTC_S24: J11.29 MC3.110
SZG_PORTC_S25: J11.30 MC3.111
SZG_PORTC_S26: J11.31 MC3.108
SZG_PORTC_S27: J11.32 MC3.109
SZG_PORTE_C2P_CLKN: MC3.150 ; port SZG_PORTE.C2P_CLKN
SZG_PORTE_C2P_CLKP: MC3.148 ; port SZG_PORTE.C2P_CLKP
SZG_PORTE_P2C_CLKN: MC3.145 ; port SZG_PORTE.P2C_CLKN
SZG_PORTE_P2C_CLKP: MC3.143 ; port SZG_PORTE.P2C_CLKP
SZG_PORTE_S0: MC3.141 ; port SZG_PORTE.S0
SZG_PORTE_S1: MC3.152 ; port SZG_PORTE.S1
SZG_PORTE_S2: MC3.154 ; port SZG_PORTE.S2
SZG_PORTE_S3: MC3.147 ; port SZG_PORTE.S3
SZG_PORTE_S4: MC3.149 ; port SZG_PORTE.S4
SZG_PORTE_S5: MC3.138 ; port SZG_PORTE.S5
SZG_PORTE_S6: MC3.140 ; port SZG_PORTE.S6
SZG_PORTE_S7: MC3.142 ; port SZG_PORTE.S7
SZG_PORTE_S8: MC3.144 ; port SZG_PORTE.S8
SZG_PORTE_S9: MC3.146 ; port SZG_PORTE.S9
VCC_PSBATT: MC3.120 TP14.1(PIN)
NetJ8_4: J8.4 R16.2
NetJ9_4: J9.4 R17.2
NetJ11_4: J11.4 R18.2

Not connected (* = marked no-connect by the designer): J8 37* 38*; J9 37* 38*; J11 37* 38*; MC3 48* 49* 101* 104* 106* 155* 156* 159* 160* 161* 163* 164* 165* 167* 169* 170*; MH12 1*; MH13 1*; MH14 1*; MH15 1*; MH16 1*; MH17 1*; U4 5(A4)* 7(B4)*; U5 3(A2)* 4(A3)* 5(A4)* 7(B4)* 8(B3)* 9(B2)*

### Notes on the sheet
- Mezzanine Connector MC3
- SYZYGY PORT A (VCCO_87_88)
- GC
- B88_L5P
- B88_L5N
- B88_L1P
- B88_L9P
- B88_L9N
- B88_L4P
- B88_L1N
- B88_L6P
- B88_L6N
- B88_L2P
- B88_L2N
- B88_L4N
- B88_L8P
- B88_L8N
- B88_L12P
- B88_L12N
- B88_L7P
- B88_L7N
- B88_L3P
- B88_L3N
- B88_L10P
- B88_L10N
- B88_L11P
- B88_L11N
- B87_L2P
- B87_L9P
- B87_L9N
- B87_L10P
- B87_L10N
- B87_L11P
- B87_L2N
- B87_L7P
- B87_L7N
- B87_L5P
- B87_L5N
- B87_L11N
- B87_L12P
- B87_L12N
- B87_L8P
- B87_L8N
- B87_L1P
- B87_L1N
- B87_L4P
- B87_L4N
- B87_L3P
- B87_L6P
- B87_L6N
- B68_L7P_N0
- B68_L7N_N1
- B87_L3N
- B68_L1P_N0
- B68_L1N_N1
- B68_L5P_N8
- SYZYGY PORT B (VCCO_68)
- B68_L19N_N1
- B68_L19P_N0
- B68_L5N_N9
- B68_T1U_N12
- MOUNTING HOLES
- B68_L21P_N4
- B68_L21N_N5
- B68_T3U_N12
- B68_L23P_N8
- B68_L12P_N10
- B68_L12N_N11
- B68_L9P_N4
- B68_L9N_N5
- Level Translator
- B68_L23N_N9
- B68_L8P_N2
- B68_L8N_N3
- B68_L20P_N2
- B68_L20N_N3
- B68_L17P_N8
- B68_L17N_N9
- B68_L22P_N6
- B68_L22N_N7
- B68_L10P_N6
- 2mm Header
- B68_L24P_N10
- B68_L24N_N11
- B68_L11P_N8
- B68_L11N_N9
- B68_L18P_N10
- B68_L10N_N7
- B68_L18N_N11
- B68_L2P_N2
- B68_L2N_N3
- B68_T0U_N12
- B68_L6P_N10
- B68_L6N_N11
- B68_T2U_N12
- B67_L5P_N8
- B67_L5N_N9
- B68_L4P_N6
- B68_L4N_N7
- B67_L6P_N10
- B67_L4P_N6
- B67_L4N_N7
- B67_L3P_N4
- B67_L3N_N5
- B67_L2P_N2
- B67_L6N_N11
- B67_L22P_N6
- (near TP14) B67_L22N_N7
- (near TP14) B67_T0U_N12
- (near TP14) B67_T1U_N12
- B67_L2N_N3
- B67_L1P_N0
- B67_L1N_N1
- B67_L8P_N2
- B67_L8N_N3
- B67_L20P_N2
- B67_L20N_N3
- B67_L14P_N2
- B67_L14N_N3
- B67_L10P_N6
- B67_L10N_N7
- B67_L15P_N4
- B67_L15N_N5
- B67_L7P_N0
- B67_L24P_N10
- B67_L24N_N11
- B67_L13P_N0
- B67_L13N_N1
- B67_T3U_N12
- SYZYGY PORT C (VCCO_67)
- B67_L7N_N1
- B67_T2U_N12
- B67_L12P_N10
- B67_L12N_N11
- B67_L19P_N0
- B67_L23P_N8
- B67_L23N_N9
- B67_L9P_N4
- B67_L9N_N5
- B67_L16P_N6
- B67_L19N_N1
- B67_L17P_N8
- B67_L17N_N9
- B67_L21P_N4
- B67_L21N_N5
- B67_L16N_N7
- B67_L18P_N10
- B67_L18N_N11
- +VDCIN: +6 to +12 VDC
- Title
- Size:
- Date:
- File:
- C
- Number:
- Time:
- Revision:
- Sheet
- of

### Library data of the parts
C18 C19 C22 C23 = 000070: as C3-C8 on sheet Expansion-MC2
C20 C21 = 001073: Ceramic capacitor; Manufacturer: Taiyo Yuden; partnumber: 001073; ValueFloat: 1E-7; x_tolerance: 10
J8 J9 J11 = 001604: 0.8mm hi-speed, high-density header (male); Manufacturer: Samtec; partnumber: 001604
J10 = 001338: Partnumber: 001338; manufacturer: Molex
MC3 = 000876: 0.5mm Double Row High Speed Socket Assembly; Partnumber: 000876; manufacturer: Samtec
MH12-MH17 = MTG: Mounting hole; partnumber: ALIGNI_IGNORE
R16 = 001549: Thick-film resistor; Manufacturer: Vishay; partnumber: 001549; ValueFloat: 210000; x_tolerance: 1
R17 = 001550: Thick-film resistor; Manufacturer: Vishay; partnumber: 001550; ValueFloat: 84500; x_tolerance: 1
R18 = 001035: Partnumber: 001035; manufacturer: Vishay; ValueFloat: 49900; x_tolerance: 1
TP14 = TP-PTH-25/45: Test point, plated through-hole, 25/45mil; partnumber: ALIGNI_IGNORE
U4 U5 = 001161: Partnumber: 001161; manufacturer: Texas Instruments

## Sheet Power.SchDoc: BRK1900 - Power
size C; Organization: Opal Kelly; Address1: 13500 SW 72nd Ave STE 100; Address3: Portland, OR  97223; Address4: http://www.opalkelly.com; DocumentNumber: xxx; Revision: 1; SheetNumber: 9; SheetTotal: 9; PageSetup: Record=PageOptions¦CenterHorizontal=True¦CenterVertical=True¦PrintScale=0.52¦XCorrection=1.00¦YCorrection=1.00¦PrintKind=0¦BorderSize=5000000¦LeftOffset=0¦BottomOffset=0¦Orientation=2¦PaperLength=1000¦PaperWidth=1000¦Scale=100¦PaperSource=7¦PrintQuality=-4¦MediaType=1¦DitherType=10¦PaperKind=Letter¦PrintScaleMode=1
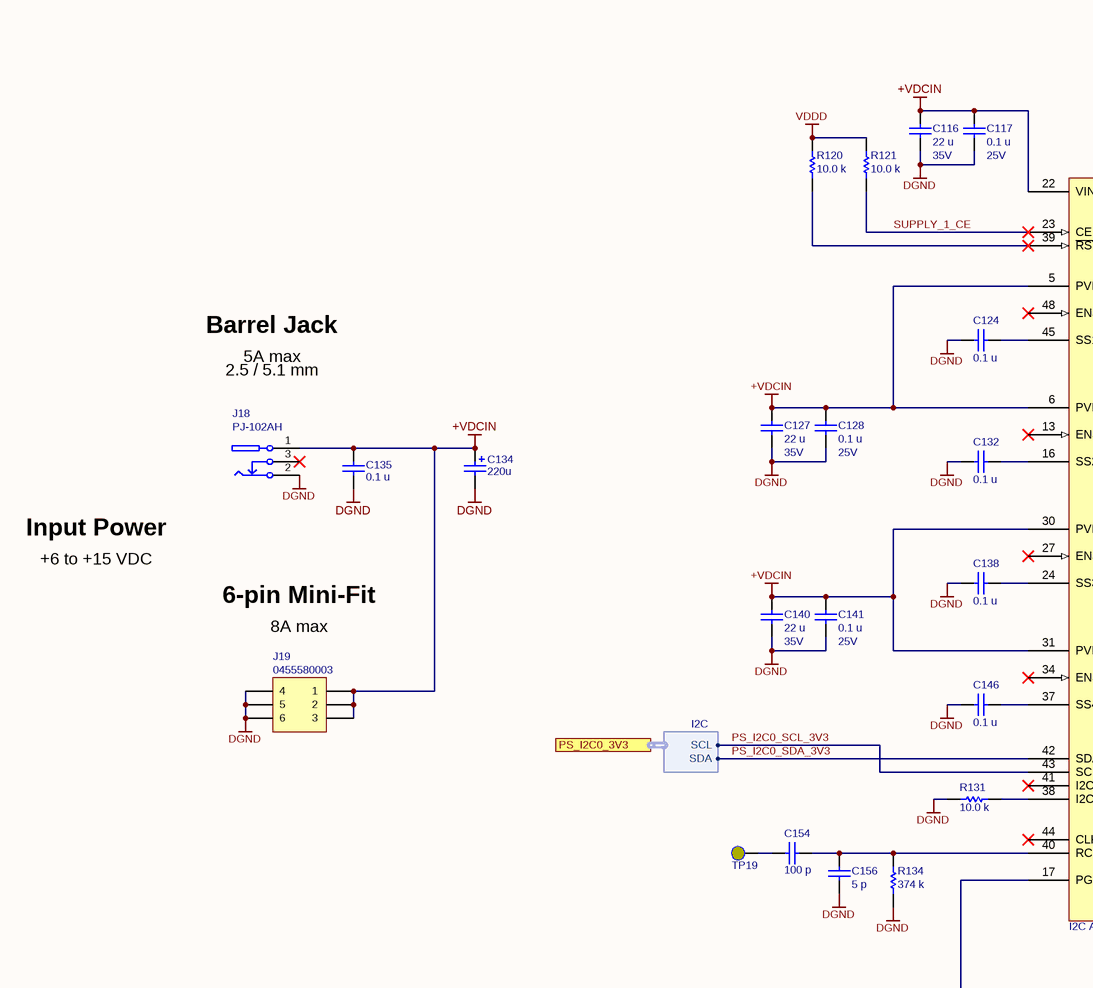
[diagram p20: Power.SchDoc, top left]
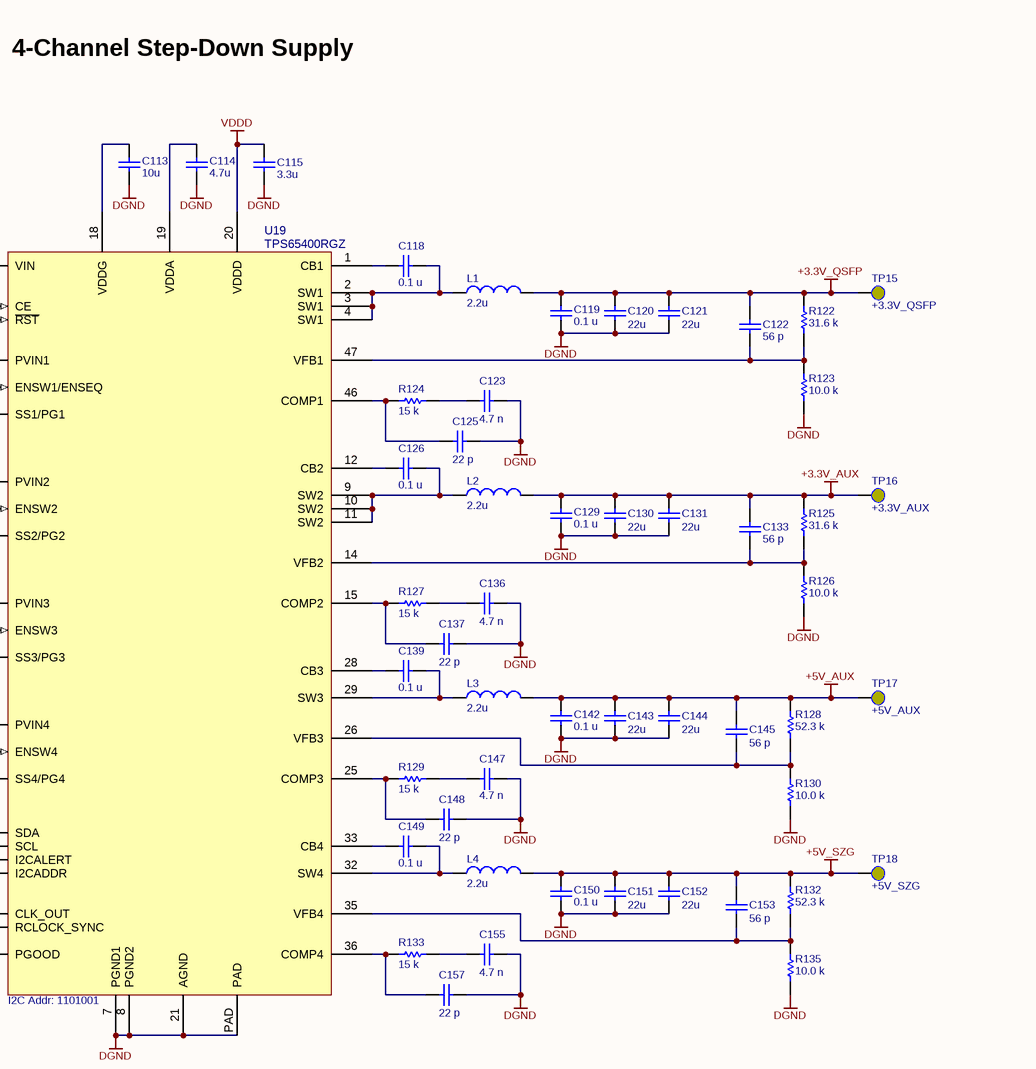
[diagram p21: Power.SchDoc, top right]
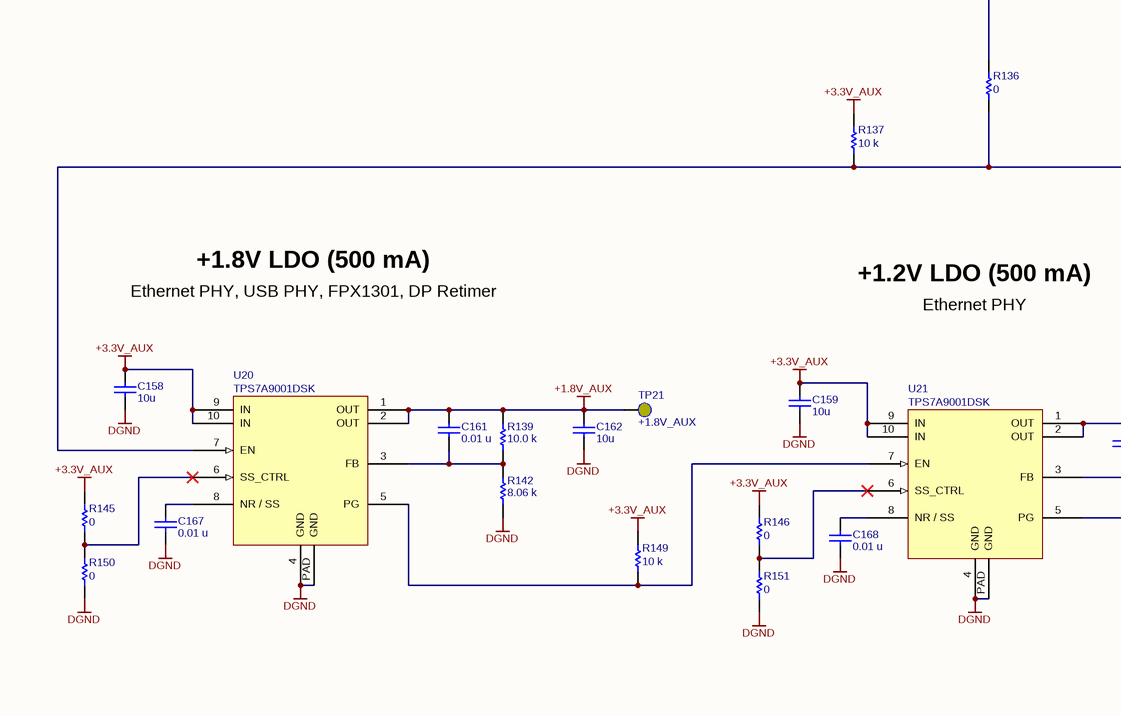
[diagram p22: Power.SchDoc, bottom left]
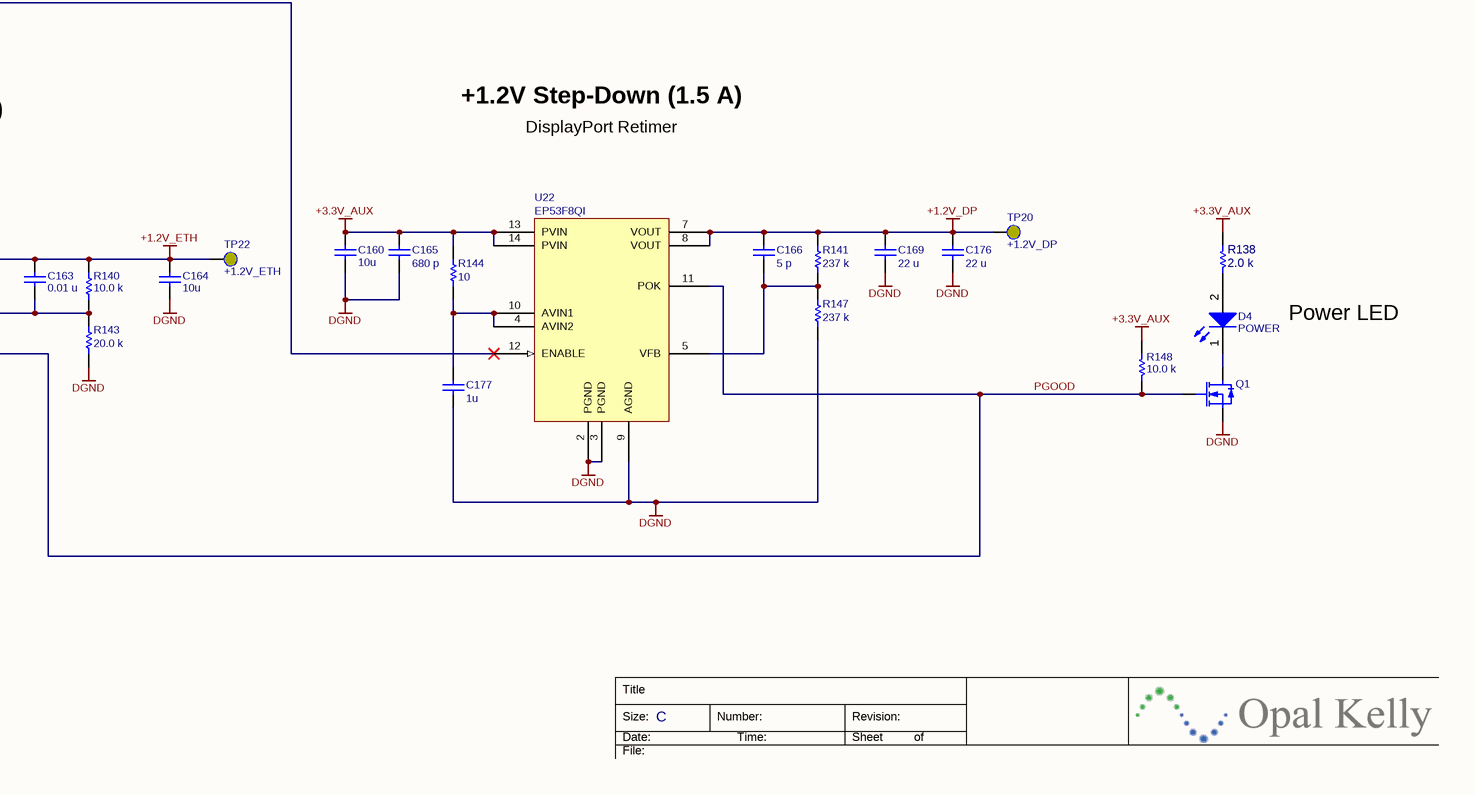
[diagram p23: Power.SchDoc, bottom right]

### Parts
C113  value 10u  [CAPC1608X09N]  (hidden comment: LMK107BJ106MALTD)
C114  value 4.7u  [CAPC1005X06A]  (hidden comment: JMK105BBJ475MV-F)
C115  value 3.3u  [CAPC1005X06A]  (hidden comment: C1005X5R1A335K050BC)
C116  value 22 u  Voltage: 35V  [CAPC3216N]  (hidden comment: C3216X5R1V226M160AC)
C117  value 0.1 u  Voltage: 25V  [CAPC1005X06A]  (hidden comment: TMK105BJ104KV-F)
C118  value 0.1 u  [CAPC1005X06A]  (hidden comment: C0402C104K8PACTU)
C119  value 0.1 u  [CAPC1005X06A]  (hidden comment: C0402C104K8PACTU)
C120  value 22u  [CAPC3216N]  (hidden comment: LMK316AB7226KL-TR)
C121  value 22u  [CAPC3216N]  (hidden comment: LMK316AB7226KL-TR)
C122  value 56 p  [CAPC1005X06A]  (hidden comment: SM-0402, 5%, 50v)
C123  value 4.7 n  [CAPC1005X06A]  (hidden comment: C0402C472K5RACTU)
C124  value 0.1 u  [CAPC1005X06A]  (hidden comment: C0402C104K8PACTU)
C125  value 22 p  [CAPC1005X06A]  (hidden comment: C0402C220J5GACTU)
C126  value 0.1 u  [CAPC1005X06A]  (hidden comment: C0402C104K8PACTU)
C127  value 22 u  Voltage: 35V  [CAPC3216N]  (hidden comment: C3216X5R1V226M160AC)
C128  value 0.1 u  Voltage: 25V  [CAPC1005X06A]  (hidden comment: TMK105BJ104KV-F)
C129  value 0.1 u  [CAPC1005X06A]  (hidden comment: C0402C104K8PACTU)
C130  value 22u  [CAPC3216N]  (hidden comment: LMK316AB7226KL-TR)
C131  value 22u  [CAPC3216N]  (hidden comment: LMK316AB7226KL-TR)
C132  value 0.1 u  [CAPC1005X06A]  (hidden comment: C0402C104K8PACTU)
C133  value 56 p  [CAPC1005X06A]  (hidden comment: SM-0402, 5%, 50v)
C134  value 220u  [CAPAE9083X70N]  (hidden comment: EEE-FK1E221P)
C135  value 0.1 u  [CAPC1005X06A]  (hidden comment: TMK105BJ104KV-F)
C136  value 4.7 n  [CAPC1005X06A]  (hidden comment: C0402C472K5RACTU)
C137  value 22 p  [CAPC1005X06A]  (hidden comment: C0402C220J5GACTU)
C138  value 0.1 u  [CAPC1005X06A]  (hidden comment: C0402C104K8PACTU)
C139  value 0.1 u  [CAPC1005X06A]  (hidden comment: C0402C104K8PACTU)
C140  value 22 u  Voltage: 35V  [CAPC3216N]  (hidden comment: C3216X5R1V226M160AC)
C141  value 0.1 u  Voltage: 25V  [CAPC1005X06A]  (hidden comment: TMK105BJ104KV-F)
C142  value 0.1 u  [CAPC1005X06A]  (hidden comment: C0402C104K8PACTU)
C143  value 22u  [CAPC3216N]  (hidden comment: LMK316AB7226KL-TR)
C144  value 22u  [CAPC3216N]  (hidden comment: LMK316AB7226KL-TR)
C145  value 56 p  [CAPC1005X06A]  (hidden comment: C0402C560J5GACTU)
C146  value 0.1 u  [CAPC1005X06A]  (hidden comment: C0402C104K8PACTU)
C147  value 4.7 n  [CAPC1005X06A]  (hidden comment: C0402C472K5RACTU)
C148  value 22 p  [CAPC1005X06A]  (hidden comment: C0402C220J5GACTU)
C149  value 0.1 u  [CAPC1005X06A]  (hidden comment: C0402C104K8PACTU)
C150  value 0.1 u  [CAPC1005X06A]  (hidden comment: C0402C104K8PACTU)
C151  value 22u  [CAPC3216N]  (hidden comment: LMK316AB7226KL-TR)
C152  value 22u  [CAPC3216N]  (hidden comment: LMK316AB7226KL-TR)
C153  value 56 p  [CAPC1005X06A]  (hidden comment: C0402C560J5GACTU)
C154  value 100 p  [CAPC1005X06A]  (hidden comment: SM-0402, 5%, 50V, NP0)
C155  value 4.7 n  [CAPC1005X06A]  (hidden comment: C0402C472K5RACTU)
C156  value 5 p  [CAPC1005X06A]  (hidden comment: GJM1555C1H5R0CB01D)
C157  value 22 p  [CAPC1005X06A]  (hidden comment: C0402C220J5GACTU)
C158  value 10u  [CAPC1608X09N]  (hidden comment: LMK107BJ106MALTD)
C159  value 10u  [CAPC1608X09N]  (hidden comment: LMK107BJ106MALTD)
C160  value 10u  [CAPC2012X14N]  (hidden comment: LMK212BJ106KG-T)
C161  value 0.01 u  [CAPC1005X06A]  (hidden comment: C0402C103K4RACTU)
C162  value 10u  [CAPC1608X09N]  (hidden comment: LMK107BJ106MALTD)
C163  value 0.01 u  [CAPC1005X06A]  (hidden comment: C0402C103K4RACTU)
C164  value 10u  [CAPC1608X09N]  (hidden comment: LMK107BJ106MALTD)
C165  value 680 p  [CAPC1005X06A]  (hidden comment: C0402C681K5RACTU)
C166  value 5 p  [CAPC1005X06A]  (hidden comment: GJM1555C1H5R0CB01D)
C167  value 0.01 u  [CAPC1005X06A]  (hidden comment: C0402C103K4RACTU)
C168  value 0.01 u  [CAPC1005X06A]  (hidden comment: C0402C103K4RACTU)
C169  value 22 u  [CAPC2012X14N]  (hidden comment: C0805C226M9PACTU)
C176  value 22 u  [CAPC2012X14N]  (hidden comment: C0805C226M9PACTU)
C177  value 1u  [CAPC1005X06A]  (hidden comment: LMK105BJ105KV-F)
D4  POWER  [CD1608-0603-PIN1-CATHODE]
J18  PJ-102AH  [CUI-PJ102A]
J19  0455580003  [0455580003]
L1  value 2.2u  [XAL60XX]  (hidden comment: XAL6030-222MEB)
L2  value 2.2u  [XAL60XX]  (hidden comment: XAL6030-222MEB)
L3  value 2.2u  [XAL60XX]  (hidden comment: XAL6030-222MEB)
L4  value 2.2u  [XAL60XX]  (hidden comment: XAL6030-222MEB)
Q1  2.2A, 30V  [SOT23-95P240X110]  (value not drawn)
R120  value 10.0 k  [RESC1005X06A]  (hidden comment: CRCW040210K0FKED)
R121  value 10.0 k  [RESC1005X06A]  (hidden comment: CRCW040210K0FKED)
R122  value 31.6 k  [RESC1005X06A]  (hidden comment: SM-0402, 1%, 1/16W)
R123  value 10.0 k  [RESC1005X06A]  (hidden comment: SM-0402, 1%, 1/16W)
R124  value 15 k  [RESC1005X06A]  (hidden comment: CRCW040215K0FKED)
R125  value 31.6 k  [RESC1005X06A]  (hidden comment: SM-0402, 1%, 1/16W)
R126  value 10.0 k  [RESC1005X06A]  (hidden comment: SM-0402, 1%, 1/16W)
R127  value 15 k  [RESC1005X06A]  (hidden comment: CRCW040215K0FKED)
R128  value 52.3 k  [RESC1005X06A]  (hidden comment: CRCW040252K3FKED)
R129  value 15 k  [RESC1005X06A]  (hidden comment: CRCW040215K0FKED)
R130  value 10.0 k  [RESC1005X06A]  (hidden comment: SM-0402, 1%, 1/16W)
R131  value 10.0 k  [RESC1005X06A]  (hidden comment: CRCW040210K0FKED)
R132  value 52.3 k  [RESC1005X06A]  (hidden comment: CRCW040252K3FKED)
R133  value 15 k  [RESC1005X06A]  (hidden comment: CRCW040215K0FKED)
R134  value 374 k  [RESC1005X06A]  (hidden comment: CRCW0402374KFKED)
R135  value 10.0 k  [RESC1005X06A]  (hidden comment: SM-0402, 1%, 1/16W)
R136  value 0  [RESC1608N]  (hidden comment: CRCW06030000Z0EA)
R137  value 10 k  [RESC1005X06A]  (hidden comment: CRCW040210K0JNED)
R138  value 2.0 k  [RESC1005X06A]  (hidden comment: CRCW04022K00FKED)
R139  value 10.0 k  [RESC1005X06A]  (hidden comment: CRCW040210K0FKED)
R140  value 10.0 k  [RESC1005X06A]  (hidden comment: CRCW040210K0FKED)
R141  value 237 k  [RESC1005X06A]  (hidden comment: CRCW0402237KFKED)
R142  value 8.06 k  [RESC1005X06A]  (hidden comment: CRCW04028K06FKED)
R143  value 20.0 k  [RESC1005X06A]  (hidden comment: CRCW040220K0FKED)
R144  value 10  [RESC1005X06A]  (hidden comment: CRCW040210R0FKED)
R145  value 0  [RESC1005X06A]  (hidden comment: CRCW04020000Z0ED)
R146  value 0  [RESC1005X06A]  (hidden comment: CRCW04020000Z0ED)
R147  value 237 k  [RESC1005X06A]  (hidden comment: CRCW0402237KFKED)
R148  value 10.0 k  [RESC1005X06A]  (hidden comment: CRCW040210K0FKED)
R149  value 10 k  [RESC1005X06A]  (hidden comment: CRCW040210K0JNED)
R150  value 0  [RESC1005X06A]  (hidden comment: CRCW04020000Z0ED)
R151  value 0  [RESC1005X06A]  (hidden comment: CRCW04020000Z0ED)
TP15  +3.3V_QSFP  [TP-SMD40]
TP16  +3.3V_AUX  [TP-SMD40]
TP17  +5V_AUX  [TP-SMD40]
TP18  +5V_SZG  [TP-SMD40]
TP19  TESTPOINT-SMD40  [TP-SMD40]  (value not drawn)
TP20  +1.2V_DP  [TP-SMD40]
TP21  +1.8V_AUX  [TP-SMD40]
TP22  +1.2V_ETH  [TP-SMD40]
U19  TPS65400RGZ  [PVQFN-48]
U20  TPS7A9001DSK  [TPS7A90]
U21  TPS7A9001DSK  [TPS7A90]
U22  EP53F8QI  [EP53F8QI]

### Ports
PS_I2C0_3V3 (harness I2C)

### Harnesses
I2C: SCL, SDA

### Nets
+1.2V_DP: C166.2 C169.2 C176.2 R141.2 TP20.1(PIN) U22.7(VOUT) U22.8(VOUT)
+1.2V_ETH: C163.2 C164.2 R140.2 TP22.1(PIN) U21.1(OUT) U21.2(OUT)
+1.8V_AUX: C161.2 C162.2 R139.2 TP21.1(PIN) U20.1(OUT) U20.2(OUT)
+3.3V_AUX: C129.2 C130.2 C131.2 C133.2 C158.2 C159.2 C160.2 C165.2 L2.2 R125.2 R137.2 R138.2 R144.2 R145.1 R146.1 R148.2 R149.2 TP16.1(PIN) U20.9(IN) U20.10(IN) U21.9(IN) U21.10(IN) U22.13(PVIN) U22.14(PVIN)
+3.3V_QSFP: C119.2 C120.2 C121.2 C122.2 L1.2 R122.2 TP15.1(PIN)
+5V_AUX: C142.2 C143.2 C144.2 C145.2 L3.2 R128.2 TP17.1(PIN)
+5V_SZG: C150.2 C151.2 C152.2 C153.2 L4.2 R132.2 TP18.1(PIN)
+VDCIN: C116.1 C117.1 C127.1 C128.1 C134.1 C135.2 C140.1 C141.1 J18.1 J19.1 J19.2 J19.3 U19.5(PVIN1) U19.6(PVIN2) U19.22(VIN) U19.30(PVIN3) U19.31(PVIN4)
DGND: C113.1 C114.1 C115.1 C116.2 C117.2 C119.1 C120.1 C121.1 C123.2 C124.2 C125.2 C127.2 C128.2 C129.1 C130.1 C131.1 C132.1 C134.2 C135.1 C136.2 C137.2 C138.2 C140.2 C141.2 C142.1 C143.1 C144.1 C146.2 C147.2 C148.2 C150.1 C151.1 C152.1 C155.2 C156.1 C157.2 C158.1 C159.1 C160.1 C162.1 C164.1 C165.1 C167.1 C168.1 C169.1 C176.1 C177.1 J18.2 J19.4 J19.5 J19.6 Q1.2(S) R123.1 R126.1 R130.1 R131.2 R134.1 R135.1 R142.1 R143.1 R147.1 R150.2 R151.2 U19.7(PGND1) U19.8(PGND2) U19.21(AGND) U19.PAD U20.4(GND) U20.PAD(GND) U21.4(GND) U21.PAD(GND) U22.2(PGND) U22.3(PGND) U22.9(AGND)
VDDD: C115.2 R120.2 R121.2 U19.20(VDDD)
PGOOD: Q1.1(G) R148.1 U21.5(PG) U22.11(POK)
PS_I2C0_SCL_3V3: U19.43(SCL) ; port PS_I2C0_3V3.SCL
PS_I2C0_SDA_3V3: U19.42(SDA) ; port PS_I2C0_3V3.SDA
SUPPLY_1_CE: R121.1 U19.23(CE)
NetC113_2: C113.2 U19.18(VDDG)
NetC114_2: C114.2 U19.19(VDDA)
NetC118_1: C118.1 U19.1(CB1)
NetC118_2: C118.2 L1.1 U19.2(SW1) U19.3(SW1) U19.4(SW1)
NetC122_1: C122.1 R122.1 R123.2 U19.47(VFB1)
NetC123_1: C123.1 R124.2
NetC124_1: C124.1 U19.45(SS1/PG1)
NetC125_1: C125.1 R124.1 U19.46(COMP1)
NetC126_1: C126.1 U19.12(CB2)
NetC126_2: C126.2 L2.1 U19.9(SW2) U19.10(SW2) U19.11(SW2)
NetC132_2: C132.2 U19.16(SS2/PG2)
NetC133_1: C133.1 R125.1 R126.2 U19.14(VFB2)
NetC136_1: C136.1 R127.2
NetC137_1: C137.1 R127.1 U19.15(COMP2)
NetC138_1: C138.1 U19.24(SS3/PG3)
NetC139_1: C139.1 U19.28(CB3)
NetC139_2: C139.2 L3.1 U19.29(SW3)
NetC145_1: C145.1 R128.1 R130.2 U19.26(VFB3)
NetC146_1: C146.1 U19.37(SS4/PG4)
NetC147_1: C147.1 R129.2
NetC148_1: C148.1 R129.1 U19.25(COMP3)
NetC149_1: C149.1 U19.33(CB4)
NetC149_2: C149.2 L4.1 U19.32(SW4)
NetC153_1: C153.1 R132.1 R135.2 U19.35(VFB4)
NetC154_1: C154.1 TP19.1(PIN)
NetC154_2: C154.2 C156.2 R134.2 U19.40(RCLOCK_SYNC)
NetC155_1: C155.1 R133.2
NetC157_1: C157.1 R133.1 U19.36(COMP4)
NetC161_1: C161.1 R139.1 R142.2 U20.3(FB)
NetC163_1: C163.1 R140.1 R143.2 U21.3(FB)
NetC166_1: C166.1 R141.1 R147.2 U22.5(VFB)
NetC167_2: C167.2 U20.8(NR_/_SS)
NetC168_2: C168.2 U21.8(NR_/_SS)
NetC177_2: C177.2 R144.1 U22.4(AVIN2) U22.10(AVIN1)
NetD4_1: D4.1(K) Q1.3(D)
NetD4_2: D4.2(A) R138.1
NetR120_1: R120.1 U19.39(~{RST})
NetR131_1: R131.1 U19.38(I2CADDR)
NetR136_1: R136.1 R137.1 U20.7(EN) U22.12(ENABLE)
NetR136_2: R136.2 U19.17(PGOOD)
NetR145_2: R145.2 R150.1 U20.6(SS_CTRL)
NetR146_2: R146.2 R151.1 U21.6(SS_CTRL)
NetR149_1: R149.1 U20.5(PG) U21.7(EN)

Not connected (* = marked no-connect by the designer): J18 3*; U19 13(ENSW2)* 27(ENSW3)* 34(ENSW4)* 41(I2CALERT)* 44(CLK_OUT)* 48(ENSW1/ENSEQ)*; U22 1(NC) 6(NC) 15(NC) 16(NC)

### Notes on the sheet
- 4-Channel Step-Down Supply
- Barrel Jack
- 5A max
- 2.5 / 5.1 mm
- +6 to +15 VDC
- Input Power
- 6-pin Mini-Fit
- 8A max
- (near U19) I2C Addr: 1101001
- +1.8V LDO (500 mA)
- Ethernet PHY, USB PHY, FPX1301, DP Retimer
- +1.2V LDO (500 mA)
- Ethernet PHY
- DisplayPort Retimer
- +1.2V Step-Down (1.5 A)
- Power LED
- Title
- Size:
- Date:
- File:
- C
- Number:
- Time:
- Revision:
- Sheet
- of

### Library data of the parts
C113 C158 C159 C162 C164 = 001346: Partnumber: 001346; manufacturer: Taiyo Yuden; ValueFloat: 1E-5; x_tolerance: 20
C114 = 000824: Partnumber: 000824; manufacturer: Taiyo Yuden; ValueFloat: 4.7E-6; x_tolerance: 20
C115 = 001926: Partnumber: 001926; manufacturer: TDK; ValueFloat: 3.3E-6; x_tolerance: 20
C116 C127 C140 = 001172: Ceramic Capacitor; Manufacturer: TDK; partnumber: 001172; Description 2: SM-1206, 35V, 20%; ValueFloat: 2.2E-5; Tolerance (%): 20; x_voltage-rating: 35
C117 C128 C141 = 001073: Ceramic capacitor; Manufacturer: Taiyo Yuden; partnumber: 001073; Description 2: 0402, 25V; ValueFloat: 1E-7; Tolerance (%): 10
C118 C119 C126 C129 C139 C142 C149 C150 = 000070: as C3-C8 on sheet Expansion-MC2
C120 C121 C130 C131 C143 C144 C151 C152 = 001284: Ceramic capacitor; Manufacturer: Taiyo Yuden; partnumber: 001284; Description 2: SM-1206, 10%, 10v, X7R; ValueFloat: 2.2E-5; Tolerance (%): 10; x_lifecycle_status: Production
C122 C133 = 001004: Partnumber: 001004; manufacturer: Kemet; manufacturer_pn: C0402C560J5GACTU; ValueFloat: 5.6E-11; id: 25707; inventory_price: 0.0024; x_temperature_characteristic: C0G; x_tolerance: 5
C123 C136 C155 = 000930: Ceramic capacitor; Manufacturer: Kemet; partnumber: 000930; Description 2: 0402, 50V; ValueFloat: 4.7E-9; Tolerance (%): 10
C124 C132 C138 C146 = 000070: Ceramic capacitor; Manufacturer: Kemet; partnumber: 000070; Description 2: SM-0402, 10%, 10v; ValueFloat: 1E-7; Tolerance (%): 10
C125 C137 C148 C157 = 000807: Ceramic capacitor; Manufacturer: Kemet; partnumber: 000807; Description 2: SM-0402, 5%, 50v, C0G; ValueFloat: 2.2E-11; Tolerance (%): 5
C134 = 001532: Polarized; Partnumber: 001532; manufacturer: Panasonic; ValueFloat: 0.00022; x_tolerance: 20; x_voltage-rating: 25
C135 = 001073: Partnumber: 001073; manufacturer: Taiyo Yuden; ValueFloat: 1E-7; x_tolerance: 10
C145 C153 = 001004: Ceramic capacitor; Manufacturer: Kemet; partnumber: 001004; Description 2: SM-0402, 5%, 50v; ValueFloat: 5.6E-11; Tolerance (%): 5
C147 = 000930: Partnumber: 000930; manufacturer: Kemet; ValueFloat: 4.7E-9; x_tolerance: 10
C154 = 000400: Partnumber: 000400; manufacturer: Kemet; manufacturer_pn: C0402C101J5GACTU; ValueFloat: 1E-10; id: 3829; inventory_price: 0.003; reorder_quantity: 200
C156 C166 = 000962: Ceramic capacitor; Manufacturer: Murata; partnumber: 000962; Description 2: SM-0402, 50V; ValueFloat: 5E-12; Tolerance (%): 3.125
C160 = 000491: Partnumber: 000491; manufacturer: Taiyo Yuden; ValueFloat: 1E-5; x_tolerance: 10
C161 C163 C167 C168 = 000295: Partnumber: 000295; manufacturer: Kemet; ValueFloat: 1E-8; x_tolerance: 10
C165 = 000963: Ceramic capacitor; Manufacturer: Kemet; partnumber: 000963; Description 2: SM-0402, 50V; ValueFloat: 6.8E-10; Tolerance (%): 10
C169 C176 = 000961: Ceramic capacitor; Manufacturer: Kemet; partnumber: 000961; Description 2: SM-0805, 6.3v; ValueFloat: 2.2E-5; Tolerance (%): 20
C177 = 000480: Ceramic capacitor; Manufacturer: Taiyo Yuden; partnumber: 000480; Description 2: SM-0402, 10%, 10v; ValueFloat: 1E-6; Tolerance (%): 10
D4 = 001433: LED; Manufacturer: Dialight; Manufacturer_PN: 598-8070-107F; partnumber: 001433; Description 2: SM-0603, green; x_lifecycle_status: Production
J18 = 000356: Partnumber: 000356; manufacturer: CUI Inc.
J19 = 001950: Partnumber: 001950; manufacturer: Molex
L1-L4 = 001543: Power inductor, 2.2uH, 7A, 12.7mOhm; Manufacturer: Coilcraft; partnumber: 001543; ValueFloat: 2.2E-6; Tolerance (%): 20; x_lifecycle_status: Production
Q1 = 001237: N-Channel MOSFET; PartNumber: 001237; manufacturer: Fairchild Semiconductor; manufacturer_pn: FDN337N; PackageDocument: 1995/1996; id: 48493; inventory_price: 0.2466
R120 R121 R148 = 001521: Thick-film resistor; Manufacturer: Vishay; partnumber: 001521; Description 2: SM-0402, 1%, 1/16W; ValueFloat: 10000; Tolerance (%): 1; x_lifecycle_status: Production
R122 R125 = 001091: Partnumber: 001091; manufacturer: Vishay; manufacturer_pn: CRCW040231K6FKED; ValueFloat: 31600; id: 32220; inventory_price: 0.0015; x_tolerance: 1
R123 R126 R130 R135 = 001521: Partnumber: 001521; manufacturer: Vishay; manufacturer_pn: CRCW040210K0FKED; ValueFloat: 10000; id: 154248; inventory_price: 0.0016; x_tolerance: 1
R124 R127 R129 R133 = 001121: Thick-film resistor; Manufacturer: Vishay; partnumber: 001121; Description 2: SM-0402, 1%, 1/16W; ValueFloat: 15000; Tolerance (%): 1
R128 R132 = 001157: Partnumber: 001157; manufacturer: Vishay; ValueFloat: 52300; x_tolerance: 1
R131 R139 R140 = 001521: Partnumber: 001521; manufacturer: Vishay; ValueFloat: 10000; x_tolerance: 1
R134 = 001618: Thick-film resistor; Manufacturer: Vishay; partnumber: 001618; Description 2: SM-0402, 1%, 1/16W; ValueFloat: 374000; Tolerance (%): 1; x_lifecycle_status: Production
R136 = 000411: Partnumber: 000411; manufacturer: Vishay
R137 R149 = 000759: Partnumber: 000759; manufacturer: Vishay; ValueFloat: 10000; x_tolerance: 5
R138 = 001162: Thick-film resistor; Manufacturer: Vishay; partnumber: 001162; Description 2: SM-0402, 1%, 1/16W; ValueFloat: 2000; Tolerance (%): 1
R141 R147 = 000965: Thick-film resistor; Manufacturer: Vishay; partnumber: 000965; Description 2: SM-0402, 1%, 1/16W; ValueFloat: 237000; Tolerance (%): 1
R142 = 001266: Partnumber: 001266; manufacturer: Vishay; ValueFloat: 8060; x_tolerance: 1
R143 = 001282: Partnumber: 001282; manufacturer: Vishay; ValueFloat: 20000; x_tolerance: 1
R144 = 000969: Thick-film resistor; Manufacturer: Vishay; partnumber: 000969; Description 2: SM-0402, 1%, 1/16W; Tolerance (%): 1
R145 R146 R150 R151 = 000755: Thick-film resistor; Manufacturer: Vishay; partnumber: 000755; x_tolerance: 1
TP15-TP22 = TESTPOINT-SMD40: Test point, surface-mount, 40mil
U19 = 001511: Partnumber: 001511; manufacturer: Texas Instruments
U20 U21 = 001932: Partnumber: 001932; manufacturer: Texas Instruments
U22 = 000960: Partnumber: 000960; manufacturer: Altera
